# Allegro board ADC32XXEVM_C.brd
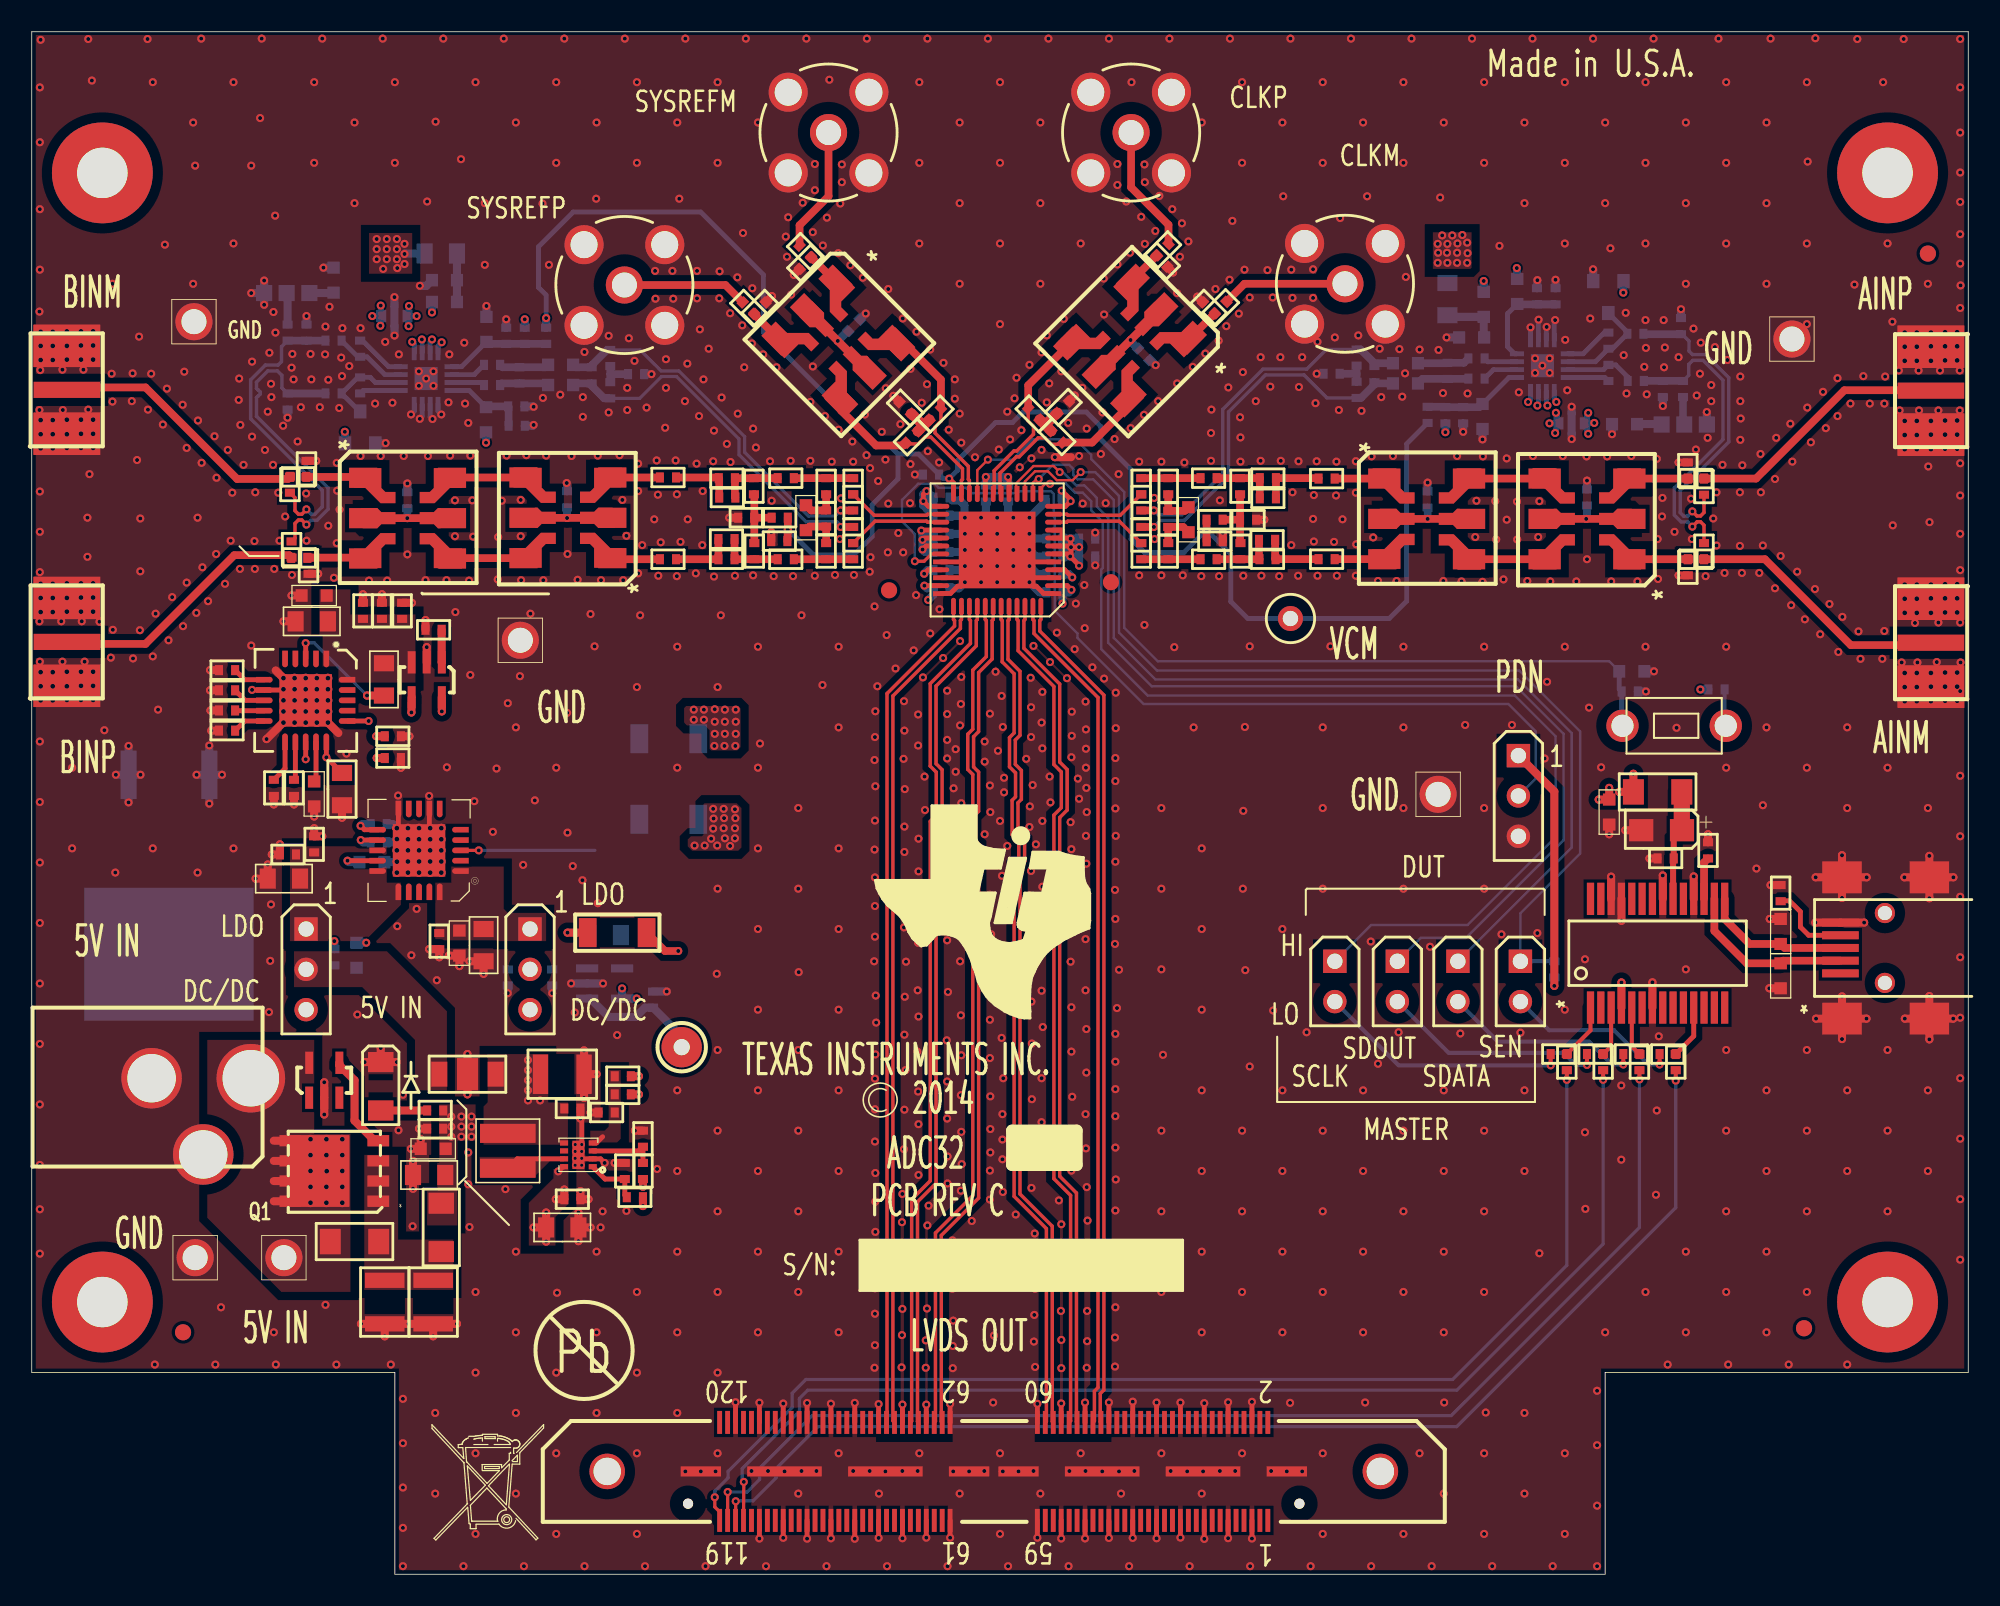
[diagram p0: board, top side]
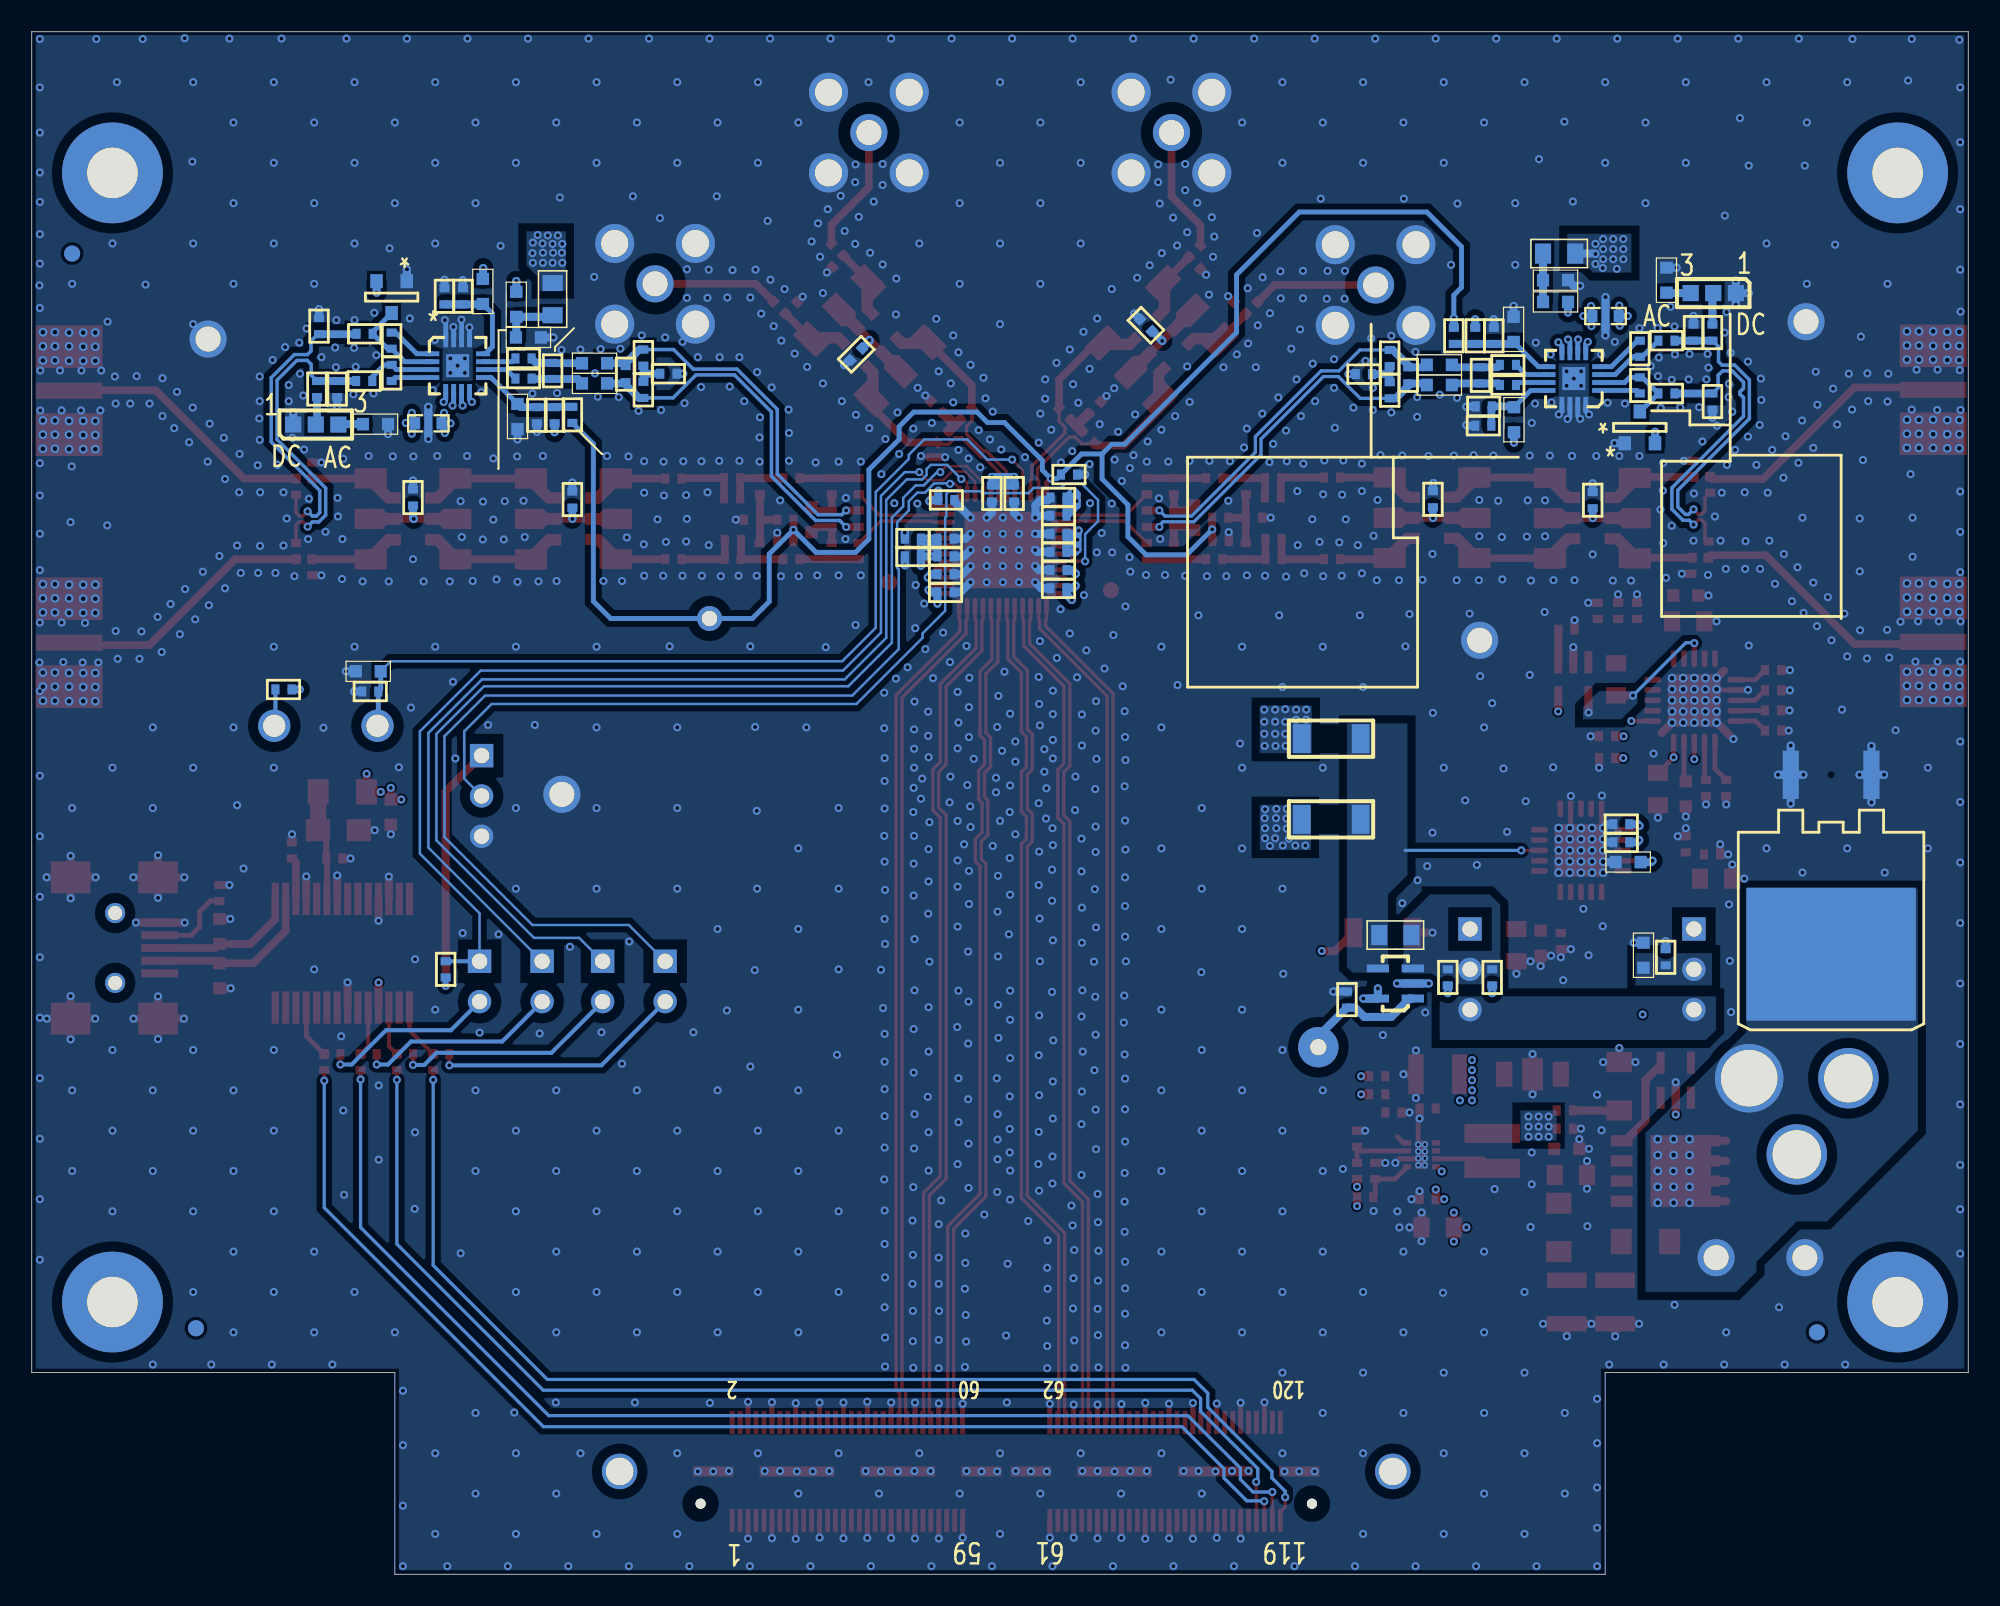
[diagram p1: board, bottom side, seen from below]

Outline 121.92 x 97.16 mm; copper layers: TOP, LYR2_GND, LYR3_PWR, LYR4_PWR, LYR5_GND, BOTTOM. Coordinates in mm from the lower left corner of the outline.
Outline path: 0,97.16 121.92,97.16 121.92,12.7 99.06,12.7 99.06,0 22.86,0 22.86,12.7 0,12.7 0,97.16

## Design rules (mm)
net group AIN: nets AINM AINP
net group BIN: nets BINM BINP
net group CLKIN: nets CLKINM CLKINP
net group DA0: nets DA0M DA0P
net group DA1: nets DA1M DA1P
net group DB0: nets DB0M DB0P
net group DB1: nets DB1M DB1P
net group DCLK: nets DCLKM DCLKP
net group DP1: nets ADCAM ADCAP
net group DP2: nets ADCBM ADCBP
net group DP3: nets AMPAINM AMPAINP
net group DP4: nets AMPBINM AMPBINP
net group DP6: nets A_INM A_INP
net group DP7: nets B_INM B_INP
net group FCLK: nets FCLKM FCLKP
net group SYSREF: nets SYSREFM SYSREFP

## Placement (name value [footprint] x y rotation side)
C1  .1uF  [0402]  81.52 69.01 180 top
C2  11pF  [0402]  71.55 66.47 270 top
C3  .1uF  [0402]  76.58 66.42 180 top
C4  .1uF  [0402]  74.48 65.07 180 top
C5  .1uF  [0402]  97.92 67.82 270 bottom
C6  .1uF  [0402]  87.88 67.69 270 bottom
C7  .1uF  [0402]  81.52 63.94 180 top
C8  .1uF  [0402]  40.06 69.08 0 top
C9  11pF  [0402]  50.01 66.5 270 top
C10  .1uF  [0402]  44.98 66.55 0 top
C11  .1uF  [0402]  47.07 65.07 0 top
C12  .1uF  [0402]  23.64 67.65 270 bottom
C13  .1uF  [0402]  33.7 67.71 270 bottom
C14  .1uF  [0402]  40.06 63.93 0 top
C29  .1uF  [0402]  57.28 64.39 0 bottom
C30  .1uF  [0402]  57.28 65.53 0 bottom
C31  .1uF  [0402]  57.28 66.67 0 bottom
C32  .1uF  [0402]  57.28 67.82 0 bottom
C33  .1uF  [0402]  66.45 65.23 0 bottom
C34  .1uF  [0402]  60.07 68.07 270 bottom
C35  .1uF  [0402]  61.47 68.07 270 bottom
C36  .1uF  [0402]  64.34 67.67 180 bottom
C37  .1uF  [0402]  64.39 65.23 180 bottom
C38  .22uF  [0402]  57.28 63.25 0 bottom
C39  .22uF  [0402]  57.28 62.1 0 bottom
C40  .22uF  [0402]  64.39 61.85 180 bottom
C41  .22uF  [0402]  64.39 62.99 180 bottom
C42  .1uF  [0402]  56.62 69.27 180 bottom
C43  .1uF  [0402]  71.21 83.43 45 top
C44  .1uF  [0402]  74.86 79.79 45 top
C45  .1uF  [0402]  64.94 73.51 45 top
C46  .1uF  [0402]  45.13 79.75 135 top
C47  .1uF  [0402]  48.7 83.32 135 top
C48  .1uF  [0402]  55 73.46 135 top
C49  10nF  [0603]  99.31 48.01 270 top
C50  .1uF  [0402]  102.87 45.09 180 top
C51  4.7uF  [TANT_A]  102.62 46.86 180 top
C52  47pF  [0603]  110.11 40.49 90 top
C53  47pF  [0603]  110.11 37.69 270 top
C54  .1uF  [0402]  105.54 45.59 90 top
C55  47uF  [1210]  22.23 17.14 270 top
C56  22uF  [1210]  25.27 17.14 90 top
C57  10uF  [0805]  25.02 25.15 180 top
C58  1.0uF  [0603]  25.27 26.8 180 top
C59  .1uF  [0402]  25.4 28.07 0 top
C60  .1uF  [0402]  34.04 23.62 180 top
C61  10uF  [0805]  33.4 21.84 0 top
C62  .1uF  [0402]  34.04 29.34 180 top
C63  22uF  [1210]  33.4 31.5 180 top
C64  1.0uF  [0603]  20.45 38.99 90 bottom
C65  .1uF  [0402]  19.05 38.86 270 bottom
C66  0.01uF  [0402]  29.97 37.59 90 bottom
C67  10uF  [0805]  15.88 43.81 180 top
C68  0.01uF  [0402]  16.13 45.34 0 top
C69  .1uF  [0402]  25.65 39.88 270 top
C70  .1uF  [0402]  17.78 45.97 270 top
C71  1.0uF  [0603]  26.92 39.75 270 top
C72  .1uF  [0402]  32.77 37.59 90 bottom
C73  47uF  [0805]  28.45 39.62 270 top
C74  1.0uF  [0603]  21.41 44.86 0 bottom
C160  0.22uF  [C-0603_X2Y]  96.95 72.49 180 bottom
C168  .01uF  [0603]  100.74 56.87 0 bottom
C169  .1uF  [0402]  66.45 64.11 0 bottom
C170  .1uF  [0402]  64.39 64.11 180 bottom
C173  .1uF  [0402]  70.01 76.84 315 bottom
C174  0  [0402]  51.77 78.67 45 bottom
C180  13pF  [0402]  89.13 75.79 270 bottom
C181  56pF  [0402]  84.53 75.59 270 bottom
C187  1.0uF  [0603]  90.65 77.9 180 bottom
C188  .1uF  [0402]  95.94 80.49 270 bottom
C189  10nF  [0603]  28.63 78.41 90 bottom
C190  .1uF  [0402]  22.73 51.41 180 top
C191  0.01uF  [0402]  22.73 52.78 180 top
C192  1.0uF  [0603]  17.78 61.65 180 top
C193  47uF  [0805]  17.63 60.02 180 top
C194  .1uF  [0402]  20.85 60.68 90 top
C195  1.0uF  [0603]  17.78 49.15 270 top
C196  0.01uF  [0402]  22.05 60.68 270 top
C197  10uF  [0805]  19.53 49.45 270 top
C198  .1uF  [0402]  23.32 60.68 270 top
C199  1.0uF  [0603]  25.98 81.51 180 bottom
C200  .1uF  [0402]  30.51 73.56 180 bottom
C205  13pF  [0402]  30.71 75.51 90 bottom
C206  56pF  [0402]  35.26 75.51 90 bottom
C207  1.0uF  [0603]  100.28 72.44 180 bottom
C208  1.0uF  [0603]  19 81.51 90 bottom
C209  10nF  [0603]  91.34 72.92 270 bottom
C210  0.22uF  [C-0603_X2Y]  22.83 79.25 180 bottom
D1  LED GREEN  [LED_1206]  21.97 30.73 90 top
D2  MBRB2515L  [DIODE_MBRB2515L]  8.64 44.7 90 bottom
D3  BAV99  [SOT_23_321]  99.26 80.44 0 bottom
D4  BAV99  [SOT_23_321]  20.68 72.24 180 bottom
F1  FUSE 2.0A 63V FAST  [1206]  20.32 20.95 0 top
FB1  60 OHM @ 100MHz  [1206]  102.36 49.28 180 top
FB2  60 OHM @ 100MHz  [1206]  25.78 21.84 270 top
FB3  27uF  [1206_BEAD_NFM31P]  27.43 31.5 180 top
FB4  1K @ 100MHz  [1806]  40.11 47.55 180 bottom
FB5  1K @ 100MHz  [1806]  40.11 52.63 180 bottom
FB7  1K @ 100MHz  [1806]  36.86 40.41 180 top
FB8  1K @ 100MHz  [0805]  89.13 80.31 90 bottom
FB9  1K @ 100MHz  [0805]  25.76 83.19 180 bottom
J1  SMA_END_RND  [SMA_RECP_250X250]  119.57 74.55 180 top
J2  SMA_END_RND  [SMA_RECP_250X250]  119.57 58.67 180 top
J3  SMA_END_RND  [SMA_RECP_250X250]  2.21 74.6 0 top
J4  SMA_END_RND  [SMA_RECP_250X250]  2.21 58.72 0 top
J9  SMB_THVT_REC  [SMA_THVT_312X312]  69.22 90.8 270 top
J10  SMB_THVT_REC  [SMA_THVT_312X312]  82.68 81.28 270 top
J11  SMB_THVT_REC  [SMA_THVT_312X312]  37.31 81.2 270 top
J12  SMB_THVT_REC  [SMA_THVT_312X312]  50.16 90.8 270 top
J13  QTH-060-01-F-D-A-RT1  [CON_SMVT_120POS_QTH_SAMTEC_RT1]  60.58 6.48 180 top
J14  USB_MINI_AB  [CON_SMRT_USBMNE20_F]  117.32 39.45 180 top
J15  CONN JACK PWR  [CON_RAPC722_JACK_THVT_3]  10.67 31.24 270 top
JP1  Jumper_1x3  [HDR_THVT_1X3_100_M]  93.6 51.56 0 top
JP2  HEADER_1x2_100_430L  [HDR_THVT_1X2_100_M]  82.04 38.61 0 top
JP3  HEADER_1x2_100_430L  [HDR_THVT_1X2_100_M]  89.79 38.61 0 top
JP4  HEADER_1x2_100_430L  [HDR_THVT_1X2_100_M]  93.73 38.61 0 top
JP5  HEADER_1x2_100_430L  [HDR_THVT_1X2_100_M]  85.98 38.61 0 top
JP6  HDR, THVT, 3POS  [HDR_THVT_1X3_100_M]  17.27 40.64 0 top
JP7  HDR, THVT, 3POS  [HDR_THVT_1X3_100_M]  31.37 40.64 0 top
L1  39nH  [0402]  77.83 67.77 0 top
L2  0  [0402]  74.47 66.42 180 top
L3  11pF  [0603]  72.82 66.42 90 top
L4  39nH  [0402]  77.77 65.15 0 top
L5  39nH  [0402]  43.79 67.82 180 top
L6  0  [0402]  47.09 66.55 0 top
L7  11pF  [0603]  48.74 66.55 90 top
L8  39nH  [0402]  43.74 65.2 180 top
L17  1uH  [IND_SM_LQH44P_1515]  29.97 26.67 90 top
L23  150nH  [0603]  86.49 76.28 180 bottom
L24  150nH  [0603]  86.49 75.01 180 bottom
L26  150nH  [0603]  33.3 74.9 0 bottom
L27  150nH  [0603]  33.3 76.17 0 bottom
NOREF  -  []  28.65 5.94 0 top
NOREF#2  -  [unnamed#2]  9.53 15.24 0 top
NOREF#3  -  []  -294.31 -159.02 0 top
NOREF#4  -  [unnamed#2]  111.58 15.49 0 top
NOREF#5  -  []  -294.54 -158.47 0 top
NOREF#6  -  [unnamed#3]  4.45 88.27 0 top
NOREF#7  -  []  99.06 0 90 top
NOREF#8  -  []  99.06 12.7 0 top
NOREF#9  -  [unnamed#3]  116.84 17.14 0 top
NOREF#10  -  []  0 12.7 0 top
NOREF#11  -  []  -276.61 355.97 0 top
NOREF#12  -  []  158.04 -35.71 0 top
NOREF#13  -  []  56.13 -12.98 0 top
NOREF#14  -  []  304.24 154.81 0 top
NOREF#15  -  []  312.88 178.16 0 top
NOREF#16  -  []  49.61 20.27 0 top
NOREF#17  -  [unnamed#3]  4.45 17.14 0 top
NOREF#18  -  [unnamed#2]  119.38 83.19 0 top
NOREF#19  -  []  -177.98 -71.46 0 top
NOREF#20  -  []  113.33 -34.38 0 top
NOREF#21  -  []  4.45 17.14 90 top
NOREF#22  -  []  0 97.16 0 top
NOREF#23  -  []  88.29 -62.33 0 top
NOREF#24  -  [unnamed#2]  53.98 61.98 0 top
NOREF#25  -  [unnamed#3]  116.84 88.27 0 top
NOREF#26  -  []  0 12.7 90 top
NOREF#27  -  []  4.45 88.27 0 top
NOREF#28  -  [unnamed#2]  67.94 62.48 0 top
NOREF#29  -  []  22.86 0 90 top
NOREF#30  -  [unnamed#2]  119.38 83.19 180 bottom
NOREF#31  -  [unnamed#2]  9.53 15.24 180 bottom
NOREF#32  -  [unnamed#2]  111.58 15.49 180 bottom
Q1  CSD18532Q5  [SON_Q5B_8]  19.05 25.4 180 top
R1  49.9  [0402]  77.83 69.04 180 top
R2  0  [0402]  74.09 69.04 180 top
R3  0  [0402]  69.85 68.53 270 top
R4  0  [0402]  104.78 69.01 180 top
R5  24.9  [0402]  76.07 68.53 270 top
R6  49.9  [0402]  71.55 68.53 270 top
R7  0  [0402]  104.27 69.52 90 top
R8  0  [0402]  104.78 63.93 180 top
R9  24.9  [0402]  76.1 64.44 270 top
R10  49.9  [0402]  71.55 64.44 270 top
R11  0  [0402]  104.27 63.42 270 top
R12  49.9  [0402]  77.8 63.94 180 top
R13  0  [0402]  74.09 63.93 180 top
R14  0  [0402]  69.85 64.44 90 top
R15  49.9  [0402]  43.76 69.03 0 top
R16  0  [0402]  47.47 69.04 0 top
R18  0  [0402]  16.84 64.02 0 top
R19  49.9  [0402]  50.01 68.53 270 top
R20  0  [0402]  17.42 63.52 270 top
R21  24.9  [0402]  45.47 68.53 270 top
R22  24.9  [0402]  45.49 64.44 270 top
R23  0  [0402]  16.78 69.12 0 top
R24  49.9  [0402]  50.01 64.44 270 top
R25  0  [0402]  17.3 69.62 90 top
R26  49.9  [0402]  43.74 63.93 0 top
R27  0  [0402]  47.47 63.93 0 top
R57  1K  [0402]  95.86 38.1 90 bottom
R58  10K  [0402]  100.61 55.6 0 bottom
R59  49.9  [0402]  71.14 82.71 315 top
R60  100  [0402]  64.55 71.64 315 top
R61  100  [0402]  63.09 73.09 315 top
R62  0  [0402]  74.1 79.75 135 top
R63  49.9  [0402]  45.84 79.75 45 top
R64  100  [0402]  56.88 73.09 45 top
R65  0  [0402]  48.72 82.58 225 top
R66  100  [0402]  55.43 71.63 45 top
R67  0  [0402]  96.65 32.26 90 top
R68  0  [0402]  101.22 32.26 90 top
R69  0  [0402]  98.93 32.26 90 top
R70  0  [0402]  103.5 32.26 90 top
R71  22  [0402]  100.71 32.77 0 top
R72  22  [0402]  96.14 32.77 0 top
R73  22  [0402]  98.43 32.77 0 top
R74  22  [0402]  103 32.77 0 top
R75  1K  [0402]  25.4 29.21 180 top
R76  0  [0402]  37.97 23.75 180 top
R77  0  [0402]  38.48 25.4 90 top
R78  105K  [0402]  37.21 30.23 180 top
R79  143K  [0402]  37.21 31.37 180 top
R80  0  [0402]  37.34 25.4 90 top
R81  0  [0402]  38.48 27.43 90 top
R82  20K  [0402]  36.2 29.08 180 top
R83  25.5K  [0402]  39.12 36.2 90 bottom
R84  0  [0402]  21.84 46.1 180 bottom
R85  0  [0402]  21.84 47.24 180 bottom
R86  0  [0402]  110.11 42.9 90 top
R87  1K  [0402]  106.07 55.73 0 bottom
R92  205  [0402]  100.97 78.13 180 bottom
R93  205  [0402]  100.99 75.16 180 bottom
R94  499  [0402]  99.26 77.7 270 bottom
R95  499  [0402]  99.26 75.67 90 bottom
R96  59  [0402]  102.69 74.65 270 bottom
R97  49.9  [0402]  103.96 74.65 90 bottom
R98  59  [0402]  103.84 78.61 90 bottom
R101  287  [0402]  83.41 74.6 90 bottom
R104  732  [0402]  32.39 78 270 bottom
R106  2  [0603]  91.41 79.98 90 bottom
R107  20K  [0603]  93.52 80.8 270 bottom
R108  49.9  [0402]  94.77 80.49 270 bottom
R109  44.2  [0402]  90.96 76.58 180 bottom
R110  44.2  [0402]  90.96 75.31 180 bottom
R113  0  [0402]  15.24 49.53 90 top
R114  0  [0402]  16.51 49.53 90 top
R115  25.5K  [0402]  25.3 59.49 180 top
R116  0  [0402]  12.29 53.14 0 top
R117  0  [0402]  12.29 54.41 0 top
R118  0  [0402]  12.29 55.68 0 top
R119  0  [0402]  12.29 56.95 0 top
R120  3.24  [0402]  69.85 67.51 270 top
R121  3.24  [0402]  69.85 65.46 270 top
R122  2  [0603]  25.98 80.14 180 bottom
R123  20K  [0603]  28.6 72.72 90 bottom
R124  49.9  [0402]  30.53 72.34 180 bottom
R125  44.2  [0402]  28.98 74.9 0 bottom
R126  44.2  [0402]  28.98 76.17 0 bottom
R127  205  [0402]  19 74.37 0 bottom
R128  205  [0402]  19 77.7 0 bottom
R129  499  [0402]  20.68 74.88 90 bottom
R130  499  [0402]  20.68 77.19 270 bottom
R131  59  [0402]  17.3 78.21 90 bottom
R132  49.9  [0402]  16.1 78.21 270 bottom
R133  59  [0402]  16.1 73.86 270 bottom
R134  287  [0402]  36.42 76.61 270 bottom
R135  0  [0402]  105.28 68.5 270 top
R136  0  [0402]  105.28 64.44 270 top
R137  0  [0402]  16.26 68.63 270 top
R138  0  [0402]  16.36 64.54 270 top
R139  0  [0402]  51.71 68.53 270 top
R141  3.24  [0402]  51.71 67.51 270 top
R142  0  [0402]  51.71 64.44 90 top
R144  3.24  [0402]  51.71 65.46 270 top
R149  732  [0402]  87.88 73.03 90 bottom
R150  11K  [0402]  89 73 270 bottom
R151  100  [0402]  90.12 73 270 bottom
R152  11K  [0402]  31.04 78 90 bottom
R153  100  [0402]  29.87 78 90 bottom
R154  287  [0402]  36.42 74.57 270 bottom
R155  0  [0402]  38.05 75.59 0 bottom
R156  287  [0402]  83.41 76.63 90 bottom
R157  0  [0402]  81.84 75.62 180 bottom
RS1  0.2  [0805]  36.07 40.26 180 bottom
RS2  0.2  [0805]  22.17 56.36 90 top
SJP1  Jumper_1x3_SMT  [SJP3_JUMPER_0603]  104.04 72.42 180 bottom
SJP2  Jumper_1x3_SMT  [SJP3_JUMPER_0603]  16.05 80.7 0 bottom
SW1  SW PUSHBUTTON  [SW_RESET_PTS635]  103.4 53.44 0 top
T1  ADT1-1WT  [TFMR_6_RF_DUAL_FOOTPRINT]  97.92 66.47 90 top
T2  ADT1-1WT  [TFMR_6_RF_DUAL_FOOTPRINT]  87.82 66.47 270 top
T3  ADT1-1WT  [TFMR_6_RF_DUAL_FOOTPRINT]  23.66 66.52 270 top
T4  ADT1-1WT  [TFMR_6_RF_DUAL_FOOTPRINT]  33.75 66.54 90 top
T9  ADT4-6WT+  [TFMR_6_RF_DUAL_FOOTPRINT]  69.15 77.7 135 top
T10  ADT4-6WT+  [TFMR_6_RF_DUAL_FOOTPRINT]  50.78 77.65 225 top
TP1  TP_THVT_060_RND-RED  [TP_THVT_060_RND]  79.25 60.2 0 top
TP4  Testloop_Red  [TESTPOINT_62DIA]  15.88 19.94 0 top
TP5  Testloop_Black  [TESTPOINT_62DIA]  10.29 19.94 0 top
TP8  RED  [TP_THVT_100_RND]  40.92 33.2 0 top
TP9  Testloop_Black  [TESTPOINT_62DIA]  30.76 58.83 0 top
TP10  Testloop_Black  [TESTPOINT_62DIA]  10.21 78.89 0 top
TP11  Testloop_Black  [TESTPOINT_62DIA]  110.82 77.8 0 top
TP12  Testloop_Black  [TESTPOINT_62DIA]  88.54 49.12 0 top
U1  ADC32XX  [QFN48_RGZ_RTC]  60.78 64.52 180 top
U2  FT245RL  [SSOP_28_413X221_26]  102.36 39.12 90 top
U3  TPS2400  [DBV5]  18.41 31.12 90 top
U4  TPS62080  [SON_DSG_8]  34.42 26.42 180 top
U5  TPS7A4700  [QFN20_RGW_P65PITCH]  24.38 45.59 180 top
U6  INA138  [DBV5]  36.07 37.21 0 bottom
U7  THS4541RGT  [QFN_16_124X124_PWRPAD]  95.11 76.12 180 bottom
U8  TPS7A4700  [QFN20_RGW_P65PITCH]  17.25 55.04 270 top
U9  INA138  [DBV5]  24.87 56.34 270 top
U10  THS4541RGT  [QFN_16_124X124_PWRPAD]  24.83 75.31 0 bottom

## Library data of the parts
C1 C7 C8 C14 = CAP_0402_0.1uF: tolerance: 10%
C2 C9 = CAP0603: tolerance: 1%
C3 C4 C10 C11 = CAP_0402_0.1uF_H: tolerance: 10%
C5 C6 C12 C13 C45 C48 C69 C173 C194 = CAP0603: tolerance: 10%
C29-C37 C42-C44 C46 C47 C169 C170 = CAP0402: tolerance: 10%
C38-C41 = CAP0402: tolerance: +/-10%
C49 C52 C53 = CAP0603
C50 C54 C55 C58 C64 C74 C187 C195 C199 C207 C208 = CAP NP_0: tolerance: 10%
C51 = CAP POL-B_10uF_10V: tolerance: 10%
C56 C63 = CAP_1210_22uF
C57 C67 C71 C192 C197 = CAP NP_1: tolerance: 10%
C59 C60 C62 C65 C66 C68 C70 C72 C188 C190 C191 C196 C198 C200 = CAPACITOR_NP_1: tolerance: 10%
C61 = CAP_1206_2.2uF: tolerance: 10%
C73 C193 = CAP0201: tolerance: 10%
C160 C210 = CAP_X2Y
C168 = CAP NP_0: tolerance: 5%
C174 = CAP0603: tolerance: 5%
C180 C205 = CAP_0402_33pF
C181 C206 = CAP_0402_18pF
C189 C209 = CAP_0603_1000pF
D1 = LED_GREEN_1206
D2 = MBRB2515L_5
D3 D4 = DIODE_BAV99
F1 = FUSE_0
FB1 FB2 FB4 FB5 FB7-FB9 = FERRITE_BEAD
FB3 = BEAD_NFM31P
J1-J4 = SMA-END_PLUG_ROUND
J9-J12 = SMA-THVT_142-0701-201_REC
J13 = CON_SMVT_120POS_QTH_SAMTEC
J14 = USB_MINI_AB_MNE20-5G5P10
J15 = CONN JACK PWR
JP1 SJP1 SJP2 = Jumper_1x3_smt
JP2-JP5 = JUMPER_1x2_100
JP6 JP7 = SMD_JUMPER_1x3
L1 L4 L5 L8 = IND_0402
L2 L6 = IND_0402_H
L3 L7 = IND0603: tolerance: 1%
L17 = IND_POWER_1.5uH
L23 L24 L26 L27 = IND0603
Q1 = CSD18532Q5B
R1 R6 R10 R12 R15 R19 R24 R26 = Res_0402_49.9: tolerance: 1%
R2 R13 R16 R27 R120 R121 R135-R138 R141 R144 = Res_0402_Zero
R3 R14 R139 R142 = Res_0402_4.99
R4 R18 R25 R62 R65 R67-R70 R84-R86 R113 R114 R116-R119 = R: tolerance: 5%
R5 R9 R21 R22 = Res_0402_24.9
R7 R8 R20 R23 R155 R157 = RES0603: tolerance: 5%
R11 = R
R57 R59-R61 R63 R64 R66 R87 R97 R104 R108 R124 R132 R149-R153 = RES0603: tolerance: 1%
R58 = R_4: tolerance: 1%
R71-R74 RS1 RS2 = R: tolerance: 1%
R75-R82 = Res_0402_1k
R83 R115 = R_1: tolerance: 1%
R92-R95 R101 R109 R110 R125-R130 R134 R154 R156 = Res_0402_249
R96 R98 R131 R133 = RES0402
R106 R107 R122 R123 = RES0603
SW1 = SW PUSHBUTTON_1
T1-T4 = TFMR_6_WBC1-1TLB
T9 T10 = XFMR_6_JTX-4-10T
TP1 = TP_THVT_060_RND-RED
TP4 TP5 TP9-TP12 = TESTLOOP_BLACK
TP8 = TESTPOINT_BLUE
U1 = ADC32XX
U2 = FT245RL_0
U3 = TPS2400
U4 = TPS62080_SON8
U5 U8 = TPS7A4700
U6 U9 = INA138
U7 U10 = THS4541RGT

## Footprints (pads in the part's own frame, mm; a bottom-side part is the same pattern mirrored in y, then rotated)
0402
  rect 0.508x0.635 smd: 1(-0.508,0) 2(0.508,0)
0603
  rect 0.762x0.787 smd: 1(-0.787,0) 2(0.787,0)
0805
  rect 1.016x1.27 smd: 1(-1.016,0) 2(1.016,0)
1206
  rect 1.321x1.6 smd: 1(-1.524,0) 2(1.524,0)
1206_BEAD_NFM31P
  rect 1.016x1.575 smd: 1(-1.778,0) 3(1.778,0)
  rect 1.321x2.032 smd: 2(0,0)
1210
  rect 0.965x2.489 smd: 1(-1.372,0) 2(1.372,0)
1806
  rect 1.118x1.829 smd: 1(-1.854,0) 2(1.854,0)
C-0603_X2Y
  rect 0.635x0.762 smd: A(-0.83,0) B(0.83,0)
  rect 0.508x0.254 smd: G1(0,0.635) G2(0,-0.635)
CON_RAPC722_JACK_THVT_3
  round 4.318 hole 3.556: 1(0,3.124)
  round 3.81 hole 3.048: 2(0,-3.124) 3(4.801,0.127)
CON_SMRT_USBMNE20_F
  round 1.27 hole 0.889 unplated: (0.65,2.2) (0.65,-2.2)
  rect 2.311x0.508 smd: 1(3.45,1.6) 2(3.45,0.8) 3(3.45,0) 4(3.45,-0.8) 5(3.45,-1.6)
  rect 2.489x2.007 smd: 6(-2.15,-4.45) 7(3.35,-4.45) 8(3.35,4.45) 9(-2.15,4.45)
CON_SMVT_120POS_QTH_SAMTEC_RT1
  round 2.235 hole 1.727: (-24.329,0) (24.35,0)
  round 0.635 hole 1.016 unplated: (-19.233,2.032) (19.258,2.032)
  rect 0.305x1.448 smd: 1(-17.244,3.086) 2(-17.244,-3.086) 3(-16.744,3.086) 4(-16.744,-3.086) 5(-16.243,3.086) 6(-16.243,-3.086) 7(-15.743,3.086) 8(-15.743,-3.086) 9(-15.243,3.086) 10(-15.243,-3.086) 11(-14.742,3.086) 12(-14.742,-3.086) 13(-14.242,3.086) 14(-14.242,-3.086) 15(-13.741,3.086) 16(-13.741,-3.086) 17(-13.241,3.086) 18(-13.241,-3.086) 19(-12.741,3.086) 20(-12.741,-3.086) 21(-12.24,3.086) 22(-12.24,-3.086) 23(-11.74,3.086) 24(-11.74,-3.086) 25(-11.239,3.086) 26(-11.239,-3.086) 27(-10.739,3.086) 28(-10.739,-3.086) 29(-10.239,3.086) 30(-10.239,-3.086) 31(-9.738,3.086) 32(-9.738,-3.086) 33(-9.238,3.086) 34(-9.238,-3.086) 35(-8.738,3.086) 36(-8.738,-3.086) 37(-8.237,3.086) 38(-8.237,-3.086) 39(-7.737,3.086) 40(-7.737,-3.086) 41(-7.236,3.086) 42(-7.236,-3.086) 43(-6.736,3.086) 44(-6.736,-3.086) 45(-6.236,3.086) 46(-6.236,-3.086) 47(-5.735,3.086) 48(-5.735,-3.086) 49(-5.235,3.086) 50(-5.235,-3.086) 51(-4.735,3.086) 52(-4.735,-3.086) 53(-4.234,3.086) 54(-4.234,-3.086) 55(-3.734,3.086) 56(-3.734,-3.086) 57(-3.233,3.086) 58(-3.233,-3.086) 59(-2.733,3.086) 60(-2.733,-3.086) 61(2.758,3.086) 62(2.758,-3.086) 63(3.259,3.086) 64(3.259,-3.086) 65(3.759,3.086) 66(3.759,-3.086) 67(4.26,3.086) 68(4.26,-3.086) 69(4.76,3.086) 70(4.76,-3.086) 71(5.26,3.086) 72(5.26,-3.086) 73(5.761,3.086) 74(5.761,-3.086) 75(6.261,3.086) 76(6.261,-3.086) 77(6.761,3.086) 78(6.761,-3.086) 79(7.262,3.086) 80(7.262,-3.086) 81(7.762,3.086) 82(7.762,-3.086) 83(8.263,3.086) 84(8.263,-3.086) 85(8.763,3.086) 86(8.763,-3.086) 87(9.263,3.086) 88(9.263,-3.086) 89(9.764,3.086) 90(9.764,-3.086) 91(10.264,3.086) 92(10.264,-3.086) 93(10.765,3.086) 94(10.765,-3.086) 95(11.265,3.086) 96(11.265,-3.086) 97(11.765,3.086) 98(11.765,-3.086) 99(12.266,3.086) 100(12.266,-3.086) 101(12.766,3.086) 102(12.766,-3.086) 103(13.266,3.086) 104(13.266,-3.086) 105(13.767,3.086) 106(13.767,-3.086) 107(14.267,3.086) 108(14.267,-3.086) 109(14.768,3.086) 110(14.768,-3.086) 111(15.268,3.086) 112(15.268,-3.086) 113(15.768,3.086) 114(15.768,-3.086) 115(16.269,3.086) 116(16.269,-3.086) 117(16.769,3.086) 118(16.769,-3.086) 119(17.269,3.086) 120(17.269,-3.086)
  rect 2.54x0.635 smd: 121(-18.438,0) 124(-1.547,0) 125(1.565,0) 128(18.456,0)
  rect 4.699x0.635 smd: 122(-13.167,0) 123(-6.817,0) 126(6.835,0) 127(13.185,0)
DBV5
  rect 1.4x0.5 smd: 1(-1.1,0.95) 2(-1.1,0) 3(-1.1,-0.95) 4(1.1,-0.95) 5(1.1,0.95)
DIODE_MBRB2515L
  rect 3.048x1.016 smd: 1(5.652,-2.54) 3(5.652,2.54)
  round 0.013 smd: 2(5.652,0)
  rect 8.382x10.668 smd: 4(-5.652,0)
HDR_THVT_1X2_100_M
  rect 1.473x1.473 hole 0.965: 1(0,0)
  round 1.473 hole 0.965: 2(0,-2.54)
HDR_THVT_1X3_100_M
  rect 1.473x1.473 hole 0.965: 1(0,0)
  round 1.473 hole 0.965: 2(0,-2.54) 3(0,-5.08)
IND_SM_LQH44P_1515
  rect 1.2x3.5 smd: 1(-1.1,0) 2(1.1,0)
LED_1206
  rect 1.27x1.6 smd: 1(-1.524,0) 2(1.524,0)
QFN20_RGW_P65PITCH
  custom 0.09x0.09 smd: 1(-2.607,1.3) 2(-2.607,0.65) 3(-2.607,0) 4(-2.607,-0.65) 5(-2.607,-1.3) 6(-1.3,-2.607) 7(-0.65,-2.607) 8(0,-2.607) 9(0.65,-2.607) 10(1.3,-2.607) 11(2.607,-1.3) 12(2.607,-0.65) 13(2.607,0) 14(2.607,0.65) 15(2.607,1.3) 16(1.3,2.607) 17(0.65,2.607) 18(0,2.607) 19(-0.65,2.607) 20(-1.3,2.607)
  rect 3.302x3.302 smd: 21(0,0)
QFN48_RGZ_RTC
  custom 0.076x0.076 smd: 1(-3.525,2.75) 2(-3.525,2.25) 3(-3.525,1.75) 4(-3.525,1.25) 5(-3.525,0.75) 6(-3.525,0.25) 7(-3.525,-0.25) 8(-3.525,-0.75) 9(-3.525,-1.25) 10(-3.525,-1.75) 11(-3.525,-2.25) 12(-3.525,-2.75) 13(-2.75,-3.525) 14(-2.25,-3.525) 15(-1.75,-3.525) 16(-1.25,-3.525) 17(-0.75,-3.525) 18(-0.25,-3.525) 19(0.25,-3.525) 20(0.75,-3.525) 21(1.25,-3.525) 22(1.75,-3.525) 23(2.25,-3.525) 24(2.75,-3.525) 25(3.525,-2.75) 26(3.525,-2.25) 27(3.525,-1.75) 28(3.525,-1.25) 29(3.525,-0.75) 30(3.525,-0.25) 31(3.525,0.25) 32(3.525,0.75) 33(3.525,1.25) 34(3.525,1.75) 35(3.525,2.25) 36(3.525,2.75) 37(2.75,3.525) 38(2.25,3.525) 39(1.75,3.525) 40(1.25,3.525) 41(0.75,3.525) 42(0.25,3.525) 43(-0.25,3.525) 44(-0.75,3.525) 45(-1.25,3.525) 46(-1.75,3.525) 47(-2.25,3.525) 48(-2.75,3.525)
  rect 4.826x4.826 smd: 49(0,0)
QFN_16_124X124_PWRPAD
  rect 0.889x0.305 smd: 1(-1.6,0.749) 2(-1.6,0.249) 3(-1.6,-0.249) 4(-1.6,-0.749) 9(1.6,-0.749) 10(1.6,-0.249) 11(1.6,0.249) 12(1.6,0.749)
  rect 0.305x0.889 smd: 5(-0.749,-1.6) 6(-0.249,-1.6) 7(0.249,-1.6) 8(0.749,-1.6) 13(0.749,1.6) 14(0.249,1.6) 15(-0.249,1.6) 16(-0.749,1.6)
  rect 1.45x1.45 smd: 17(0,0)
SJP3_JUMPER_0603
  rect 1.016x1.016 smd: 1(-1.422,0) 2(0,0) 3(1.422,0)
SMA_RECP_250X250
  rect 4.191x1.016 smd: 1(0,0)
  rect 4.191x2.667 smd: 2(0,2.769) 3(0,-2.769) 4(0,2.769) 5(0,-2.769)
SMA_THVT_312X312
  round 2.337 hole 1.575: 1(0,0)
  round 2.464 hole 1.702: 2(-2.54,2.54) 3(2.54,2.54) 4(2.54,-2.54) 5(-2.54,-2.54)
SON_DSG_8
  rect 0.508x0.33 smd: 1(-0.903,0.75) 2(-0.903,0.25) 3(-0.903,-0.25) 4(-0.903,-0.75) 5(0.903,-0.75) 6(0.903,-0.25) 7(0.903,0.25) 8(0.903,0.75)
  rect 0.762x1.778 smd: 9(0,0)
SON_Q5B_8
  rect 1.372x0.711 smd: 1(-2.767,1.905) 2(-2.767,0.635) 3(-2.767,-0.635) 4(-2.767,-1.905) 5(2.767,-1.905) 6(2.767,-0.635) 7(2.767,0.635) 8(2.767,1.905)
SOT_23_321
  rect 0.787x0.889 smd: 1(-0.953,-1.003) 2(0.953,-1.003) 3(0,1.003)
SSOP_28_413X221_26
  rect 2.032x0.457 smd: 1(-3.425,4.225) 2(-3.425,3.575) 3(-3.425,2.925) 4(-3.425,2.275) 5(-3.425,1.625) 6(-3.425,0.975) 7(-3.425,0.325) 8(-3.425,-0.325) 9(-3.425,-0.975) 10(-3.425,-1.625) 11(-3.425,-2.275) 12(-3.425,-2.925) 13(-3.425,-3.575) 14(-3.425,-4.225) 15(3.425,-4.225) 16(3.425,-3.575) 17(3.425,-2.925) 18(3.425,-2.275) 19(3.425,-1.625) 20(3.425,-0.975) 21(3.425,-0.325) 22(3.425,0.325) 23(3.425,0.975) 24(3.425,1.625) 25(3.425,2.275) 26(3.425,2.925) 27(3.425,3.575) 28(3.425,4.225)
SW_RESET_PTS635
  round 2.032 hole 1.397: 1(-3.251,0) 2(3.251,0)
TANT_A
  rect 1.524x1.397 smd: 1(-1.283,0) 2(1.283,0)
TESTPOINT_62DIA
  round 2.337 hole 1.575: 1(0,0)
TFMR_6_RF_DUAL_FOOTPRINT
  rect 1.27x1.778 smd: 1(-2.54,-2.794) 2(0,-2.794) 3(2.54,-2.794) 4(2.54,2.794) 5(0,2.794) 6(-2.54,2.794)
TP_THVT_060_RND
  round 1.575 hole 0.965: 1(0,0)
TP_THVT_100_RND
  round 2.54 hole 1.016: 1(0,0)
unnamed#2
  round 1.016 smd: 1(0,0)
unnamed#3
  round 6.35 hole 3.175: (0,0)

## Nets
1.8V: JP6.3(PIN3) JP7.3(PIN3)
2.8V_IN: C67.1 C68.2 C70.2 JP6.1(PIN1) U5.13(EN) U5.15(IN2) U5.16(IN1)
5.0V_IN: D2.4 F1.1 J15.1 Q1.5(D5) Q1.6(D6) Q1.7(D7) Q1.8(D8) TP4.1(TP) U3.5(VIN)
5VIN: C49.1 C57.1 C58.1 C59.2 C60.2 C61.1 C190.2 C191.2 C197.1 FB1.2 FB2.1 R75.1 R76.1 R77.1 U4.8(VIN) U6.5(V+) U8.13(EN) U8.15(IN2) U8.16(IN1) U9.5(V+)
+VCC: FB8.2 FB9.2 RS2.1 U8.3(SENSE) U9.4(VIN-)
AVDD1.8V: C29.1 C30.1 C31.1 C32.1 C33.1 C34.1 C35.1 C36.1 C37.1 C169.1 C170.1 FB5.1 U1.6(AVDD#6) U1.7(AVDD#7) U1.8(AVDD#8) U1.9(AVDD#9) U1.12(AVDD#12) U1.17(AVDD#17) U1.20(AVDD#20) U1.25(AVDD#25) U1.28(AVDD#28) U1.29(AVDD#29) U1.30(AVDD#30)
DVDD1.8V: C38.1 C39.1 C40.1 C41.1 FB4.1 JP1.1(PIN1) R57.1 R87.1 U1.2(DVDD#2) U1.4(DVDD#4) U1.33(DVDD#33) U1.35(DVDD#35)
GND: C3.1 C4.1 C5.1 C6.1 C10.1 C11.1 C12.1 C13.1 C29.2 C30.2 C31.2 C32.2 C33.2 C34.2 C35.2 C36.2 C37.2 C38.2 C39.2 C40.2 C41.2 C42.2 C45.2 C48.2 C49.2 C50.2 C51.2 C52.2 C53.2 C54.2 C55.2 C56.1 C57.2 C58.2 C59.1 C60.1 C61.2 C62.1 C63.1 C64.2 C65.1 C66.1 C67.2 C68.1 C69.2 C70.1 C71.2 C72.1 C73.2 C74.2 C160.G1 C160.G2 C168.2 C169.2 C170.2 C173.2 C174.2 C187.2 C188.1 C189.2 C190.1 C191.1 C192.2 C193.2 C194.2 C195.2 C196.1 C197.2 C198.1 C199.2 C200.1 C207.2 C208.2 C209.2 C210.G1 C210.G2 D1.2(CATHODE) D2.1 D2.3 D3.1 D4.1 FB3.2 J1.2(SHIELD2) J1.3(SHIELD3) J1.4(SHIELD4) J1.5(SHIELD1) J2.2(SHIELD2) J2.3(SHIELD3) J2.4(SHIELD4) J2.5(SHIELD1) J3.2(SHIELD2) J3.3(SHIELD3) J3.4(SHIELD4) J3.5(SHIELD1) J4.2(SHIELD2) J4.3(SHIELD3) J4.4(SHIELD4) J4.5(SHIELD1) J9.2(GND#2) J9.3(GND#3) J9.4(GND#4) J9.5(GND#5) J10.2(GND#2) J10.3(GND#3) J10.4(GND#4) J10.5(GND#5) J11.2(GND#2) J11.3(GND#3) J11.4(GND#4) J11.5(GND#5) J12.2(GND#2) J12.3(GND#3) J12.4(GND#4) J12.5(GND#5) J13.5 J13.6 J13.11 J13.12 J13.17 J13.18 J13.23 J13.24 J13.29 J13.30 J13.35 J13.36 J13.41 J13.42 J13.47 J13.48 J13.53 J13.54 J13.59 J13.60 J13.61 J13.62 J13.67 J13.68 J13.73 J13.74 J13.79 J13.80 J13.85 J13.86 J13.91 J13.92 J13.97 J13.98 J13.103 J13.104 J13.109 J13.110 J13.116 J13.121(GND#121) J13.122(GND#122) J13.123(GND#123) J13.124(GND#124) J13.125(GND#125) J13.126(GND#126) J13.127(GND#127) J13.128(GND#128) J14.5(GND) J14.6(GND1) J14.7(GND2) J14.8(GND3) J14.9(GND4) J15.2 J15.3 JP1.3(PIN3) R7.2 R11.2 R20.2 R25.2 R58.2 R59.2 R62.2 R63.2 R65.2 R80.2 R81.2 R82.2 R83.2 R84.1 R85.1 R86.2 R96.2 R98.2 R108.1 R113.1 R114.1 R115.2 R116.1 R117.1 R118.1 R119.1 R124.1 R131.2 R133.2 R151.2 R153.2 R155.2 R157.2 SJP1.1(PIN1) SJP2.1(PIN1) TP5.1(TP) TP9.1(TP) TP10.1(TP) TP11.1(TP) TP12.1(TP) U1.1(GND#1) U1.3(GND#3) U1.5(GND#5) U1.32(GND#32) U1.34(GND#34) U1.36(GND#36) U1.49(THERMPAD) U2.7(GND#7) U2.18(GND#18) U2.21(GND#21) U2.25(AGND) U2.26(TEST) U3.2(GND) U4.2(GND) U4.9(THERMPAD) U5.7(GND) U5.10(0P4V) U5.21(PWRPAD) U6.2(GND) U7.13(VS1-) U7.14(VS2-) U7.15(VS3-) U7.16(VS4-) U7.17(PWRPAD) U8.7(GND) U8.21(PWRPAD) U9.2(GND) U10.13(VS1-) U10.14(VS2-) U10.15(VS3-) U10.16(VS4-) U10.17(PWRPAD)
A_INM: J2.1(CENTER) R8.1 R136.2
A_INP: J1.1(CENTER) R4.1 R135.1
ADCAM: C181.2 L24.2 R101.1 R121.1
ADCAP: C181.1 L23.2 R120.2 R156.2
ADCBM: C206.1 L26.2 R144.1 R154.2
ADCBP: C206.2 L27.2 R134.1 R141.2
AINM: R14.2 R121.2 U1.10(INP_A)
AINP: R3.2 R120.1 U1.11(INM_A)
AMPAINM: R93.1 R96.1 R97.2 R136.1
AMPAINP: R92.1 R98.1 R135.2
AMPBINM: R127.1 R133.1 R138.1
AMPBINP: R128.1 R131.1 R132.2 R137.2
B_INM: J3.1(CENTER) R23.1 R137.1
B_INP: J4.1(CENTER) R18.1 R138.2
BINM: R142.2 R144.2 U1.27(INP_B)
BINP: R139.2 R141.1 U1.26(INM_B)
CLKINM: R61.1 T9.4(SECONDARY) U1.19(CLKM)
CLKINP: R60.2 T9.6(SECONDARY_DOT) U1.18(CLKP)
CLOCK_INM: C44.2 J10.1(CENTER)
CLOCK_INP: C43.2 J9.1(CENTER)
DA0M: J13.44 U1.48(DA0M)
DA0P: J13.46 U1.47(DA0P)
DA1M: J13.50 U1.46(DA1M)
DA1P: J13.52 U1.45(DA1P)
DB0M: J13.70 U1.40(DB0M)
DB0P: J13.72 U1.39(DB0P)
DB1M: J13.76 U1.38(DB1M)
DB1P: J13.78 U1.37(DB1P)
DCLKM: J13.56 U1.44(DCLKM)
DCLKP: J13.58 U1.43(DCLKP)
FCLKM: J13.64 U1.42(FCLKM)
FCLKP: J13.66 U1.41(FCLKP)
FPGA_CSEL: J13.115 R70.1
FPGA_SCLK: J13.119 R67.1
FPGA_SDI: J13.117 R68.1
FPGA_SDO: J13.113 R69.1
FTDI_VCCIO1.8V: FB7.1 U2.4(VCCIO)
PDA: C188.2 R107.2 R108.2 U7.12(PD)
PDB: C200.2 R123.2 R124.2 U10.12(PD)
PDN: JP1.2(PIN2) U1.31(PDN)
RESET: C168.1 R58.1 SW1.1 U1.21(RESET)
SCLK: JP2.2 R72.1
SDATA: JP3.2 R71.1
SDOUT: JP5.2 R73.1
SEN: JP4.2 R74.1
SYSREF_INM: C47.2 J12.1(CENTER)
SYSREF_INP: C46.2 J11.1(CENTER)
SYSREFM: R66.1 T10.4(SECONDARY) U1.23(SYSREFM)
SYSREFP: R64.2 T10.6(SECONDARY_DOT) U1.22(SYSREFP)
U5_SENSE: FB4.2 FB5.2 RS1.1 U5.3(SENSE) U6.4(VIN-)
VAMPA: C160.A C160.B D3.2 R106.2 R107.1 R150.2 U7.5(VS1+) U7.6(VS2+) U7.7(VS3+) U7.8(VS4+)
VAMPB: C210.A C210.B D4.2 R122.2 R123.1 R152.2 U10.5(VS1+) U10.6(VS2+) U10.7(VS3+) U10.8(VS4+)
VCM: C4.2 C11.2 C42.1 L2.2 L6.2 R104.1 R149.1 TP1.1(TP) U1.24(VCM)
VCM_AMPA: C209.1 R149.2 R150.1 R151.1 U7.9(VOCM)
VCM_AMPB: C189.1 R104.2 R152.1 R153.1 U10.9(VOCM)
N16255310: C5.2 T1.2(SECONDARY_CT) T1.5(NC)
N16255380: T1.6(PRIMARY_DOT) T2.4(PRIMARY)
N16255412: T1.4(PRIMARY) T2.6(PRIMARY_DOT)
N16255546: C6.2 T2.2(SECONDARY_CT) T2.5(NC)
N16275326: C12.2 T3.2(SECONDARY_CT) T3.5(NC)
N16275406: C14.1 T4.1(SECONDARY_DOT)
N16275410: T3.4(PRIMARY) T4.6(PRIMARY_DOT)
N16275430: T3.6(PRIMARY_DOT) T4.4(PRIMARY)
N16275564: C13.2 T4.2(SECONDARY_CT) T4.5(NC)
N17995731: C7.1 T2.3(SECONDARY)
N18036747: R4.2 R7.1 T1.3(SECONDARY)
N18037025: R8.2 R11.1 T1.1(SECONDARY_DOT)
N18037341: R18.2 R20.1 T3.3(SECONDARY)
N18145356: C44.1 R62.1 T9.1(PRIMARY)
N18145361: C43.1 R59.1 T9.3(PRIMARY_DOT)
N18152532: C1.1 T2.1(SECONDARY_DOT)
N18152657: C8.1 T4.3(SECONDARY)
N18154317: JP2.1 U1.13(SCLK)
N18154319: JP5.1 U1.16(SDOUT)
N18154320: JP4.1 R57.2 U1.15(SEN)
N18154541: JP3.1 U1.14(SDATA)
N18158256: C50.1 C51.1 FB1.1 U2.20(VCC)
N18158298: R69.2 R73.2 U2.3(D2)
N18158304: R67.2 R72.2 U2.1(D0)
N18158332: C53.1 J14.2(D-) U2.16(USBDM)
N18158362: C54.1 U2.17(3V3OUT)
N18158372: C52.1 J14.3(D+) U2.15(USBDP)
N18158488: R68.2 R71.2 U2.5(D1)
N18172592: R23.2 R25.1 T3.1(SECONDARY_DOT)
N18176897: C3.2 L2.1 R5.2 R9.1
N18176915: C2.1 L3.2 R6.2
N18176926: C2.2 L3.1 R10.1
N18176961: R2.2 R3.1 R6.1
N18176965: R10.2 R13.2 R14.1
N18176992: L1.1 R1.2 R2.1 R5.1
N18176994: L4.1 R9.2 R12.2 R13.1
N18177028: C1.2 L1.2 R1.1
N18177046: C7.2 L4.2 R12.1
N18177748: C10.2 L6.1 R21.2 R22.1
N18177758: C9.1 L7.2 R19.2
N18177777: C9.2 L7.1 R24.1
N18177812: R16.2 R19.1 R139.1
N18177816: R24.2 R27.2 R142.1
N18177835: L5.1 R15.2 R16.1 R21.1
N18177837: L8.1 R22.2 R26.2 R27.1
N18177879: C8.2 L5.2 R15.1
N18177897: C14.2 L8.2 R26.1
N18182829: C47.1 R65.1 T10.1(PRIMARY)
N18182834: C46.1 R63.1 T10.3(PRIMARY_DOT)
N18184820: R76.2 R80.1 U4.1(EN)
N18184826: R77.2 R81.1 U4.3(MODE)
N18184858: L17.1 U4.7(SW)
N18184878: C62.2 C63.2 FB3.1 L17.2 R78.1 R79.1 U4.5(VOS)
N18184911: R78.2 R79.2 R82.1 U4.4(FB)
N18184929: C66.2 C72.2 FB7.2 JP7.2(PIN2) RS1.2 U6.3(VIN+)
N18184992: C55.1 C56.2 F1.2 FB2.2 Q1.1(S1) Q1.2(S2) Q1.3(S3)
N18185086: C69.1 C71.1 C73.1 JP7.1(PIN1) U5.1(OUT1) U5.20(OUT2)
N18185106: C74.1 U5.14(NR)
N18185155: R84.2 U5.12(0P1V)
N18185175: R85.2 U5.11(0P2V)
N18185335: C64.1 C65.2 FB3.3 JP6.2(PIN2)
N18185416: R83.1 TP8.1(TP) U6.1(OUT)
N18185709: Q1.4(G) U3.4(GATE)
N18185817: D1.1(ANODE) R75.2
N18186843: R70.2 R74.2 U2.11(D3)
N18187243: J14.4(ID) R86.1
N18187932: R87.2 SW1.2
N18195117: C45.1 R60.1 R61.2
N18195272: C173.1 T9.2(PRIMARY_CT) T9.5(SECONDARY_CT)
N18195497: C48.1 R64.1 R66.2
N18195560: C174.1 T10.2(PRIMARY_CT) T10.5(SECONDARY_CT)
N18236051: C180.1 L23.1 R109.2
N18236057: C180.2 L24.1 R110.2
N18238916: C187.1 FB8.1 R106.1
N18248026: R110.1 U7.10(VOUT+)
N18248246: R109.1 U7.11(VOUT-)
N18248498: R93.2 R95.2 U7.3(VIN-)
N18248506: R95.1 U7.4(FB+)
N18248596: D3.3 R92.2 R94.2 U7.2(VIN+)
N18248639: R94.1 U7.1(FB-)
N18254985: C192.1 C193.1 C194.1 C196.2 C198.2 RS2.2 U8.1(OUT1) U8.20(OUT2) U9.3(VIN+)
N18255095: C195.1 U8.14(NR)
N18255144: R114.2 U8.12(0P1V)
N18255168: R113.2 U8.11(0P2V)
N18255172: R116.2 U8.10(0P4V)
N18255251: R115.1 U9.1(OUT)
N18258500: R117.2 U8.9(0P8V)
N18258503: R118.2 U8.8(1P6V)
N18258506: R119.2 U8.6(3P2V)
N18271567: C199.1 FB9.1 R122.1
N18273924: C205.1 L26.1 R125.2
N18273934: C205.2 L27.1 R126.2
N18274097: R126.1 U10.10(VOUT+)
N18274103: R125.1 U10.11(VOUT-)
N18274115: R128.2 R130.2 U10.3(VIN-)
N18274119: R130.1 U10.4(FB+)
N18274129: D4.3 R127.2 R129.2 U10.2(VIN+)
N18274135: R129.1 U10.1(FB-)
N18283030: C207.1 SJP1.3(PIN3)
N18283930: R97.1 SJP1.2(PIN2)
N18284096: C208.1 SJP2.3(PIN3)
N18284104: R132.1 SJP2.2(PIN2)
N18358536: R134.2 R154.1 R155.1
N18359182: R101.2 R156.1 R157.1

Pads without a net: D2 2; J13 1 2 3 4 7 8 9 10 13 14 15 16 19 20 21 22 25 26 27 28 31 32 33 34 37 38 39 40 43 45 49 51 55 57 63 65 69 71 75 77 81 82 83 84 87 88 89 90 93 94 95 96 99 100 101 102 105 106 107 108 111 112 114 118 120; J14 1; NOREF#2 1; NOREF#4 1; NOREF#18 1; NOREF#24 1; NOREF#28 1; NOREF#30 1; NOREF#31 1; NOREF#32 1; U2 2 6 8 9 10 12 13 14 19 22 23 24 27 28; U3 1 3; U4 6; U5 2 4 5 6 8 9 17 18 19; U8 2 4 5 17 18 19

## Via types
v1: diameter 0.508, hole 0.254, TOP to BOTTOM, 1764 vias
v2: diameter 0.559, hole 0.305, TOP to BOTTOM, 185 vias
v3: diameter 0.406, hole 0.203, TOP to BOTTOM, 8 vias

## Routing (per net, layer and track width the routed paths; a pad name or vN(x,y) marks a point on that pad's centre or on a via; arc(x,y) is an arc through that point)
5.0V_IN: length 28.8
  TOP w0.254: v2(17.55,26.4) v2(17.55,27.4) ; v2(17.55,26.4) v2(17.55,25.4) ; v2(17.55,26.4) v2(18.55,26.4) ; v2(17.55,27.4) 17.45,27.3 Q1.5 ; v2(17.55,27.4) v2(18.55,27.4) ; v2(18.57,25.39) 18.57,26.38 v2(18.55,26.4) ; v2(18.57,25.39) 18.58,25.4 v2(19.55,25.4) ; v2(18.57,25.39) 17.56,25.39 v2(17.55,25.4) ; v2(18.57,25.39) 18.55,25.37 v2(18.55,24.4) ; v2(19.55,24.4) v2(18.55,24.4) ; v2(19.55,24.4) v2(19.55,25.4) ; v2(19.55,24.4) v2(19.55,23.4) v2(18.55,23.4) ; v2(18.55,24.4) v2(17.55,24.4) ; v2(18.55,24.4) v2(18.55,23.4) ; v2(17.55,25.4) v2(17.55,24.4) ; v2(18.55,26.4) v2(19.55,26.4) ; v2(18.55,26.4) v2(18.55,27.4) ; v2(18.55,27.4) v2(19.55,27.4) v2(19.55,26.4) ; v2(19.55,26.4) v2(19.55,25.4) ; Q1.8 17.45,23.49 v2(17.55,23.4) ; v2(18.55,23.4) v2(17.55,23.4) ; v2(17.55,23.4) v2(17.55,24.4)
  TOP w0.508: Q1.5 15.24,27.3 ; Q1.7 15.24,24.77 ; Q1.6 15.24,26.04 ; Q1.8 15.24,23.49
5VIN: length 17
  TOP w0.305: v1(33.15,25.37) 33.44,25.67 U4.8 ; U8.15 v1(18.55,51.46) C197.1 ; U8.13 v1(17.25,51.33) ; U8.16 v1(21.21,53.74)
  TOP w0.508: C61.1 v1(32.39,20.95) ; C61.1 v1(31.6,21.84) ; C61.1 v1(32.39,22.78) ; v1(32.99,23.62) C60.2 v1(33.53,24.23) ; v1(99.31,49.53) C49.1 v1(98.65,48.79) ; C190.2 v1(21.72,51.41) ; C191.2 v1(21.69,52.78) ; v1(99.95,49.28) FB1.2 v1(100.84,50.42) ; R76.1 v1(38.48,23.19) ; R77.1 v1(38.48,24.41) ; U9.5 v1(25.82,54.35)
  BOTTOM w0.508: v1(38.09,36.26) U6.5 v1(37.17,36.9)
  vias: v1(26.42,28.83) v1(26.42,28.19) v1(26.42,27.56) v1(27.05,28.83) v1(27.05,28.19) v1(27.05,27.56) v1(27.69,28.83) v1(27.69,28.19) v1(27.69,27.56)
+VCC: length 9.6
  TOP w0.305: U8.3 v1(17.25,58.65)
  TOP w0.508: RS2.1 v1(21.11,55.35) ; U9.4 v1(23.9,54.28)
  BOTTOM w0.203: v1(17.25,58.65) 17.27,58.67 17.78,58.67 v1(21.11,55.35)
  BOTTOM w0.508: v1(23.47,83.16) 23.5,83.19 FB9.2
  vias: v1(21.72,84.1) v1(21.72,83.46) v1(21.72,82.83) v1(22.12,82.22) v1(22.35,84.1) v1(22.35,83.46) v1(22.35,82.83) v1(22.99,84.1) v1(22.99,83.46) v1(22.99,82.83) v1(23.01,82.27) v1(23.47,83.79) v1(23.47,82.52) v1(88.52,83.79) v1(88.54,83.24) v1(88.52,82.6) v1(88.8,84.33) v1(89.13,83.79) v1(89.1,83.24) v1(89.13,82.6) v1(89.43,84.33) v1(89.76,83.82) v1(89.74,83.24) v1(89.74,82.6) v1(90.07,84.35) v1(90.37,83.87) v1(90.37,82.6) v1(90.4,83.21)
AVDD1.8V: length 38.1
  TOP w0.305: U1.9 64.87,65.77 64.87,65.27 ; U1.28 56.04,65.77 v1(56.01,65.74) ; U1.8 64.87,65.27 ; 64.87,65.27 65.37,65.27 v1(65.41,65.23) 65.41,64.77 ; U1.20 60.03,69.07 v1(60.07,69.11) ; v1(61.47,69.11) 61.53,69.05 U1.17 ; U1.7 65.41,64.77 ; 65.41,64.77 65.41,64.72 v1(65.43,64.69) ; v1(65.43,64.69) 65.43,64.16 v1(65.38,64.11) ; v1(65.43,64.69) v1(65.94,64.69) ; v1(56.08,65.15) 56.2,65.27 U1.29 ; v1(65.38,64.11) 65.22,64.27 U1.6 ; v1(65.38,64.11) 65.94,63.55 v1(65.94,63.53) ; U1.30 56.31,64.77 v1(56.08,64.54) ; v1(56.34,68.22) 56.13,68.02 v1(56.13,67.59) 56.46,67.27 U1.25 ; U1.12 65.08,67.27 v1(65.41,67.59) 65.41,67.69 v1(64.85,68.25)
  BOTTOM w0.508: v1(56.01,65.74) 56.08,65.66 56.08,65.53 ; v1(65.41,67.59) 65.33,67.67 C36.1 v1(64.85,68.25) ; 56.34,67.31 56.34,67.11 C31.1 C32.1 56.74,67.82 v1(56.34,68.22) ; 56.34,67.31 v1(56.34,68.22) ; 56.34,67.31 56.13,67.31 v1(56.13,67.59) 56.13,68.02 v1(56.34,68.22) ; 56.77,64.95 C30.1 56.21,65.53 ; 56.77,64.95 C29.1 ; 56.77,64.95 56.21,64.95 56.21,65.53 ; 56.77,64.95 C29.1 ; 64.9,64.72 C37.1 v1(65.41,65.23) C33.1 v1(65.94,64.69) ; 64.9,64.72 65.41,64.72 v1(65.43,64.69) v1(65.94,64.69) ; 64.9,64.72 C170.1 v1(65.38,64.11) C169.1 ; v1(65.94,64.69) C169.1 ; 56.21,65.53 56.08,65.53 ; 56.08,65.53 v1(56.08,65.15) v1(56.08,64.54) 56.24,64.39 C29.1 ; C169.1 v1(65.94,63.53) ; C35.1 C34.1 v1(60.07,69.11) v1(61.47,69.11) C35.1
  vias: v1(41.68,54.46) v1(41.68,53.82) v1(42.32,54.46) v1(42.32,53.82) v1(42.98,52.17) v1(43,54.48) v1(43,53.7) v1(43,52.93) v1(43.64,54.46) v1(43.64,53.7) v1(43.64,52.93) v1(43.61,52.17) v1(44.32,54.46) v1(44.32,53.7) v1(44.32,52.93) v1(44.3,52.17)
DVDD1.8V: length 25.6
  TOP w0.305: v1(65.51,62.79) 65.03,63.27 U1.4 ; v1(56.18,63.02) 56.43,63.27 U1.33 ; U1.35 v1(56.2,62.27) ; U1.2 65.19,62.27 v1(65.46,62)
  TOP w0.508: JP1.1 95.86,49.3 v1(95.86,37.06)
  BOTTOM w0.305: R57.1 v1(95.86,37.06)
  BOTTOM w0.508: R87.1 v1(105.05,55.73) ; v1(56.44,61.37) 56.77,61.7 C39.1 56.36,62.1 v1(56.2,62.27) ; C38.1 56.41,63.25 v1(56.18,63.02) ; v1(64.9,61.14) C40.1 65.3,61.85 v1(65.46,62) ; v1(65.51,62.79) 65.3,62.99 C41.1
  vias: v1(41.73,45.9) v1(42.37,45.9) v1(42.77,46.33) v1(42.9,48.21) v1(42.93,47.6) v1(42.9,46.96) v1(43.15,45.9) v1(43.56,48.21) v1(43.59,47.62) v1(43.56,46.99) v1(43.64,46.36) v1(43.97,45.87) v1(44.27,48.18) v1(44.27,46.99) v1(44.27,46.36) v1(44.3,47.62)
GND: length 224.5
  TOP w0.305: J13.104 v1(47.31,10.75) ; J13.103 v1(47.31,2.29) ; J13.79 v1(53.32,2.29) ; v1(58.75,63.5) 58.48,63.77 U1.32 ; J13.80 v1(53.32,10.72) ; J13.17 v1(73.82,2.23) ; U1.36 57.27,61.78 57.84,61.78 58.29,62.23 58.5,62.23 v1(58.75,62.48) 58.47,62.77 U1.34 ; 22.82,46.99 v2(22.98,46.99) 23.08,47.09 U5.10 ; J13.36 v1(69.32,10.87) ; J13.86 v1(51.82,10.79) ; U1.5 63.08,63.77 v1(62.81,63.5) ; J13.47 v1(66.31,2.26) ; J13.42 v1(67.82,10.82) ; J13.59 v1(63.31,2.3) ; v3(34.63,27.07) 34.63,28.62 v1(34.54,28.7) ; J13.73 v1(54.82,2.27) ; J13.30 v1(70.82,10.82) ; J13.110 v1(45.81,10.81) ; v3(34.62,26.2) 34.65,26.17 U4.2 35.81,26.17 v1(36.07,25.91) ; J13.54 v1(64.81,10.76) ; J13.24 v1(72.32,10.82) ; J13.98 v1(48.81,10.79) ; v1(13.87,55.7) 13.88,55.69 U8.7 15.8,55.69 v2(15.85,55.74) ; U1.1 64.29,61.78 63.7,61.78 63.25,62.23 63.07,62.23 v1(62.81,62.48) 63.1,62.77 U1.3 ; J13.116 v1(44.31,10.83) ; J13.48 v1(66.31,10.82) ; J13.61 v1(57.82,2.3) ; J13.68 v1(56.32,10.69) ; J13.109 v1(45.81,2.25) ; J13.11 v1(75.32,2.27) ; v2(25.08,46.99) 25.03,47.04 U5.7 ; J13.6 v1(76.82,10.86) ; J13.92 v1(50.31,10.74) ; J13.18 v1(73.82,10.78) ; J13.67 v1(56.32,2.3) ; J13.35 v1(69.32,2.29) ; J13.12 v1(75.32,10.84) ; J13.23 v1(72.32,2.31) ; J13.41 v1(67.82,2.28) ; 25.78,47.02 v2(25.78,46.99) ; J13.29 v1(70.82,2.26) ; J13.5 v1(76.82,2.25) ; J13.97 v1(48.81,2.24) ; J13.60 v1(63.31,10.73) ; J13.91 v1(50.31,2.26) ; J13.74 v1(54.82,10.69) ; J13.62 v1(57.82,10.73) ; J13.53 v1(64.81,2.25) ; J13.85 v1(51.82,2.24)
  TOP w0.483: R7.2 v1(103.68,70.03) ; R11.2 v1(103.68,62.92)
  TOP w0.508: C56.1 v1(23.72,15.77) C55.2 ; C56.1 v1(26.77,15.77) ; C56.1 v1(25.27,14.99) ; R118.1 v1(11.23,55.68) ; U2.18 v1(104.64,43.95) ; J14.9 v1(120.98,35) ; J14.9 v1(117.93,35) ; J14.9 v1(119.47,33.69) ; J14.9 v1(119.47,36.41) ; v1(25.02,39.37) C69.2 v1(25.65,38.86) ; C54.2 v1(105.54,46.61) ; C190.1 v1(23.24,50.8) ; v2(15.85,53.64) 15.82,53.64 v1(14.78,52.6) ; v1(112.29,41.05) J14.5 v1(115.37,41.05) ; D1.2 v1(21.97,33.15) ; D1.2 v1(22.99,32.26) ; D1.2 v1(20.96,32.26) ; C197.2 v1(19.53,47.65) ; C49.2 v1(99.31,46.61) ; v1(28.45,37.82) C73.2 v1(27.56,38.61) ; C55.2 v1(20.73,15.77) ; C55.2 v1(22.23,14.99) ; v1(65.66,74.24) 65.3,73.89 C45.2 ; J14.7 v1(113.97,42.6) ; J14.7 v1(112.31,43.9) ; J14.7 v1(113.97,45.29) ; J14.7 v1(115.52,43.9) ; C191.1 v1(23.77,52.78) ; C196.1 v1(22.05,61.72) ; v1(35.05,23.62) C60.1 v1(34.54,24.13) ; R81.2 v1(37.97,27.94) ; J14.6 v1(119.47,45.25) ; J14.6 v1(120.99,43.9) ; J14.6 v1(119.47,42.58) ; J14.6 v1(117.9,43.9) ; C61.2 v1(34.42,22.78) ; C61.2 v1(34.42,20.98) ; C61.2 v1(35.18,21.84) ; C3.1 v1(77.6,66.42) ; v1(54.25,74.22) 54.64,73.84 C48.2 ; v1(24,24.28) C57.2 v1(24,26.04) ; R63.2 v1(46.6,80.5) ; R119.1 v1(11.23,56.95) ; v1(15.62,45.97) C68.1 v1(15.11,45.34) ; v1(46.56,65.63) C11.1 ; R65.2 v1(47.98,81.85) ; C63.1 v1(35.56,31.5) ; C63.1 v1(34.77,32.99) ; C63.1 v1(34.77,30) ; v1(18.41,28.96) U3.2 v1(18.41,30.99) ; U9.2 v1(24.87,58.39) ; R20.2 v1(18.03,63.01) ; v2(15.85,56.44) 15.36,56.93 ; v1(24.49,27.41) C58.2 v1(23.88,26.8) ; R115.2 v1(24.79,60.1) ; C194.2 v1(20.85,61.72) ; U2.26 v1(99.44,43.94) ; v1(27.43,32.77) FB3.2 v1(27.43,30.23) ; v1(26.92,38.3) C71.2 v1(26.26,38.96) ; J14.8 v1(113.97,33.71) ; J14.8 v1(113.97,36.4) ; J14.8 v1(112.34,35) ; J14.8 v1(115.51,35) ; v1(14.86,44.7) C67.2 v1(14.1,43.81) ; U2.25 v1(100.09,41.16) ; v1(64.41,70.36) 65.43,70.36 ; v1(18.29,46.48) C70.1 v1(17.78,46.99) ; C10.1 v1(43.92,66.55) ; R117.1 v1(11.25,54.41) ; R80.2 v1(36.7,25.91) ; R114.1 v1(16.51,48.49) ; R113.1 v1(15.24,48.49) ; C59.1 v1(24.38,28.07) ; R59.2 v1(71.86,82) ; C52.2 v1(109.42,41.27) ; C192.2 v1(16.36,61.65) ; v2(18.65,53.64) 19.3,52.98 ; R86.2 v1(109.47,43.41) ; R82.2 v1(35.18,29.08) ; C50.2 v1(101.85,45.09) ; C4.1 v1(74.99,65.6) ; R25.2 v1(17.91,70.13) ; R116.1 v1(11.3,53.14) ; R62.2 v1(73.38,80.47) ; U2.21 v1(102.69,44.01) ; C195.2 v1(17.78,47.73) ; C198.1 v1(23.93,61.19) ; C51.2 v1(100.33,46.86) ; C53.2 v1(109.4,36.91) ; C62.1 v1(34.54,28.7) ; C193.2 v1(15.85,60.02) ; U2.7 v1(102.04,37.28)
  BOTTOM w0.305: U7.15 95.36,78.54 v1(95.38,78.56) ; U10.13 25.58,73.25 v1(25.78,73.05) ; U10.16 24.08,73.26 v1(23.88,73.05) ; U7.13 94.36,78.53 v1(94.36,78.54) ; v1(95.91,78.99) 95.86,78.94 U7.16 ; U7.14 94.86,79.01 v1(94.87,79.02) ; v1(24.43,72.77) 24.43,72.79 24.58,72.94 U10.15 ; U10.14 25.08,72.89 25.2,72.77 25.22,72.77 v1(25.23,72.76)
  BOTTOM w0.483: C210.G1 22.83,80.04 ; R157.2 v1(80.9,75.62) ; C210.G2 22.84,78.61 22.84,78.47 ; 22.26,71.23 v1(22.28,71.25) ; R155.2 v1(39.01,75.59) ; C207.2 v1(99.49,71.81)
  BOTTOM w0.508: C188.1 v1(95.94,81.53) ; SJP2.1 v1(13.82,80.7) ; SJP2.1 v1(14.63,81.48) ; SJP2.1 v1(14.63,79.96) ; C39.2 58.37,62.1 v1(58.75,62.48) ; R85.1 22.73,47.24 v2(22.98,46.99) ; R108.1 v1(94.79,81.51) ; 58.72,66.67 58.72,67.34 58.42,67.64 57.96,67.64 C32.2 ; 58.72,66.67 C31.2 ; 58.72,66.67 58.72,66.57 v1(58.75,66.55) ; D2.3 v1(11.18,52.2) ; D2.3 v1(11.18,48.54) ; D2.3 v1(11.98,50.36) ; D2.3 v1(10.38,50.36) ; C29.2 58.62,64.39 v1(58.75,64.52) ; C173.2 70.44,76.48 v1(70.76,76.16) ; C38.2 58.5,63.25 v1(58.75,63.5) ; v1(33.68,68.73) 33.7,68.71 C13.1 ; C74.2 22.96,44.86 v2(22.99,44.88) ; C12.1 23.64,68.7 v1(23.65,68.71) ; R124.1 31.55,72.34 v1(31.6,72.39) ; v1(62.81,66.55) 63.83,67.56 C36.2 ; D4.1 22.26,71.23 ; 6.1,50.36 v1(6.1,52.17) ; 6.1,50.36 v1(5.3,50.36) ; 6.1,50.36 v1(6.85,50.36) ; 6.1,50.36 v1(6.1,48.62) ; C35.2 61.47,66.88 v1(61.8,66.55) ; C209.2 v1(91.34,71.48) ; C66.1 v1(29.97,36.6) ; R151.2 v1(90.12,71.96) ; 97.92,68.33 v1(97.92,68.88) ; C189.2 v1(28.63,79.88) ; C37.2 63.12,65.23 v1(62.81,65.53) ; v2(22.99,46.3) 22.78,46.1 R84.1 ; R58.2 v1(101.63,55.6) ; C64.2 v1(21.06,39.78) ; C200.1 31.57,73.56 v1(31.6,73.53) ; C72.1 v1(32.77,36.6) ; v1(103.84,79.68) R98.2 ; SJP1.1 v1(105.46,73.2) ; v1(62.81,64.52) 63.22,64.11 C170.2 ; C160.G1 v1(96.95,73.53) ; C34.2 60.07,66.85 v1(59.77,66.55) ; C41.2 63.32,62.99 v1(62.81,63.5) ; R96.2 v1(102.69,73.58) ; C42.2 v1(55.6,69.27) ; C6.1 v1(87.88,68.76) ; C40.2 63.45,61.85 v1(62.81,62.48) ; 22.84,78.47 v1(22.84,78.02) ; 19,82.3 v1(18.36,82.3) ; 22.83,80.04 v1(22.83,80.44) ; D3.1 98.31,82.18 v1(98.3,82.19) ; C199.2 24.84,81.15 v1(24.43,81.15) ; C174.2 v1(52.51,79.41) ; C160.G2 v1(96.95,71.5) ; C187.2 v1(89.08,77.9) ; R131.2 v1(17.3,79.25) ; C30.2 v1(58.75,65.53) ; v1(66.95,63.55) C169.2 ; R133.2 v1(16.1,72.85) ; v1(66.95,65.61) C33.2 ; C65.1 v1(19.05,39.88) ; R153.2 v1(29.87,79.04) ; v1(33.96,37.21) U6.2 v1(35.97,37.21) ; R83.2 v1(39.98,36.7) ; C168.2 v1(102.13,56.87)
  vias: v1(0.48,79.53) v1(0.48,73.33) v1(0.48,60.02) v1(0.56,96.65) v1(0.51,93.65) v1(0.51,90.2) v1(0.51,85.98) v1(0.51,82.17) v1(0.53,75.84) v1(0.51,68.2) v1(0.51,65.66) v1(0.51,63.12) v1(0.51,57.48) v1(0.51,52.45) v1(0.51,48.64) v1(0.51,44.83) v1(0.51,41.02) v1(0.51,37.21) v1(0.51,33.4) v1(0.51,29.59) v1(0.51,25.78) v1(0.51,22.99) v1(0.51,20.19) v1(1.85,60.02) v1(1.93,75.87) v1(1.96,73.33) v1(1.93,57.48) v1(2.54,50.8) v1(2.54,45.72) v1(3.15,60.02) v1(3.25,75.87) v1(3.33,57.48) v1(3.56,96.7) v1(3.56,73.36) v1(3.51,66.55) v1(3.51,64.08) v1(3.63,69.29) v1(3.78,94.08) v1(4.27,59.99) v1(4.57,53.16) v1(4.98,57.73) v1(5.08,81.28) v1(5.03,75.62) v1(5.08,73.86) v1(5.11,59.49) v1(5.26,44.2) v1(6.35,75.64) v1(6.3,73.89) v1(6.38,57.68) v1(6.63,70.18) v1(6.76,77.95) v1(6.83,66.5) v1(6.83,63.17) v1(6.81,59.46) v1(7.29,96.7) v1(7.32,73.36) v1(7.52,75.62) v1(7.62,93.98) v1(7.62,57.81) v1(7.62,45.72) v1(7.75,13.21) v1(7.8,60.5) v1(7.95,54.46) v1(8.26,72.42) v1(8.38,83.74) v1(8.51,74.68) v1(8.61,58.83) v1(8.84,61.54) v1(9.5,73.66) v1(9.53,59.72) v1(9.6,75.74) v1(9.75,70.94) v1(9.75,62.46) v1(10.16,91.44) v1(10.16,81.28) v1(10.29,88.72) v1(10.36,60.55) v1(10.46,72.67) v1(10.44,66.55) v1(10.44,44.2) v1(10.67,96.72) v1(10.69,70) v1(10.74,63.42) v1(11.1,61.29) v1(11.51,71.68) v1(11.56,13.21) v1(11.63,69.06) v1(11.61,64.26) v1(11.91,16.81) v1(12.17,62.38) v1(12.34,70.82) v1(12.52,65.1) v1(12.62,68.12) v1(12.7,93.98) v1(12.7,83.82) v1(12.7,45.72) v1(13.06,75.31) v1(13.03,73.96) v1(13.13,72.39) v1(13.11,63.32) v1(13.34,69.88) v1(13.82,88.72) v1(13.87,76.38) v1(13.87,71.65) v1(13.82,58.5) v1(14.07,68.15) v1(14.02,65.07) v1(14.05,63.32) v1(14.38,91.72) v1(14.48,96.72) v1(14.68,70.82) v1(14.86,73.23) v1(14.96,76.94) v1(14.94,35.41) v1(15.06,74.98) v1(15.09,74.14) v1(15.06,42.19) v1(15.01,38.63) v1(15.19,69.88) v1(15.21,79.5) v1(15.27,63.32) v1(15.24,15.24) v1(15.32,85.57) v1(15.34,78.21) v1(15.37,13.21) v1(15.52,68.12) v1(15.6,65.1) v1(15.82,72.34) v1(15.95,66.62) v1(16.36,76) v1(16.38,62.94) v1(16.41,76.86) v1(16.48,75.26) v1(16.74,71.35) v1(16.94,73.51) v1(17.27,68.07) v1(17.3,65.1) v1(17.55,76.86) v1(17.6,75.26) v1(17.78,93.98) v1(17.78,88.9) v1(18.14,73.51) v1(18.29,96.72) v1(18.49,78.59) v1(18.47,76.83) v1(18.49,16.97) v1(18.67,75.23) v1(18.67,66.04) v1(18.75,79.83) v1(19.02,62.76) v1(19.18,13.21) v1(19.2,70) v1(19.23,68.25) v1(19.2,64.95) v1(19.35,73.46) v1(19.38,67.06) v1(19.48,76.63) v1(19.56,78.49) v1(19.53,75.46) v1(19.81,51.69) v1(19.99,76.1) v1(20.32,91.44) v1(20.32,86.36) v1(20.5,35.26) v1(20.7,78.49) v1(20.7,70.43) v1(21.23,62.59) v1(21.62,73.74) v1(21.97,70.43) v1(22.1,96.72) v1(22.25,77.62) v1(22.38,62.59) v1(22.61,13.21) v1(22.71,73.79) v1(22.86,93.98) v1(22.86,88.9) v1(23.06,49.05) v1(23.01,40.82) v1(23.09,27.97) v1(23.11,76.83) v1(23.37,30.2) v1(23.37,11.05) v1(23.37,8.25) v1(23.37,5.46) v1(23.37,2.92) v1(23.37,0.51) v1(23.42,70.43) v1(23.65,64.24) v1(23.9,38.99) v1(23.98,21.92) v1(24.23,41.91) v1(24.37,75.77) v1(24.37,74.85) v1(24.79,62.61) v1(24.89,86.46) v1(24.83,75.31) v1(24.94,70.43) v1(25.02,49.02) v1(25.29,75.77) v1(25.29,74.85) v1(25.43,91.49) v1(25.4,10.16) v1(25.4,5.08) v1(25.5,37.41) v1(25.91,96.72) v1(26.11,62.61) v1(26.14,50.83) v1(26.29,76.83) v1(26.24,73.81) v1(26.34,70.46) v1(26.64,67.64) v1(26.64,65.38) v1(26.67,60.6) v1(27.03,89.13) v1(27.18,0.51) v1(27.23,77.57) v1(27.28,73.74) v1(27.48,72.52) v1(27.48,26.57) v1(27.48,24.56) v1(27.53,62.59) v1(27.56,21.87) v1(27.61,70.46) v1(27.61,56.64) v1(27.74,67.64) v1(27.79,65.35) v1(27.86,48.69) v1(27.94,93.98) v1(27.94,17.78) v1(27.94,12.7) v1(27.94,7.62) v1(27.94,2.54) v1(28.52,86.36) v1(28.52,82.47) v1(29.03,46.76) v1(29.26,50.75) v1(29.36,65.33) v1(29.34,62.66) v1(29.59,67.61) v1(29.72,96.72) v1(29.82,24.26) v1(29.9,70.46) v1(29.97,54.86) v1(30.48,91.44) v1(30.48,53.34) v1(30.48,20.32) v1(30.48,15.24) v1(30.48,10.16) v1(30.48,5.08) v1(30.78,67.67) v1(30.78,65.38) v1(30.73,56.57) v1(30.81,62.61) v1(30.94,44.68) v1(30.99,0.51) v1(31.14,70.48) v1(31.39,60.5) v1(31.67,48.74) v1(32.16,86.33) v1(32.18,74.09) v1(32.21,62.61) v1(32.39,70.46) v1(32.56,82.47) v1(33.02,93.98) v1(33.02,88.9) v1(33.02,50.8) v1(33.07,17.73) v1(33.02,12.7) v1(33.02,7.62) v1(33.02,2.54) v1(33.27,74.3) v1(33.53,96.72) v1(33.73,64.26) v1(33.71,54.25) v1(33.73,46.71) v1(33.99,70.43) v1(34.06,44.6) v1(34.19,35.38) v1(34.37,62.64) v1(34.67,43.71) v1(34.7,74.14) v1(34.7,72.9) v1(34.8,76.99) v1(34.8,0.51) v1(35.18,60.48) v1(35.43,58.45) v1(35.56,91.44) v1(35.53,86.64) v1(35.56,20.32) v1(35.56,15.24) v1(35.56,10.16) v1(35.64,70.46) v1(35.64,42.27) v1(35.84,62.61) v1(35.81,21.84) v1(35.94,22.86) v1(36.32,78) v1(36.32,73.18) v1(36.86,33.96) v1(37.01,70.48) v1(37.19,67.67) v1(37.24,62.61) v1(37.34,96.72) v1(37.49,74.73) v1(37.49,73.33) v1(37.44,65.41) v1(37.44,22.89) v1(37.59,77.85) v1(37.95,76.43) v1(38.1,93.98) v1(38.1,88.9) v1(38.18,69.95) v1(38.18,68.22) v1(38.18,63.04) v1(38.1,55.88) v1(38.1,17.78) v1(38.1,12.7) v1(38.1,7.62) v1(38.1,2.54) v1(38.3,60.4) v1(38.43,64.82) v1(38.61,0.51) v1(38.71,73.48) v1(39.19,66.45) v1(39.24,82.09) v1(39.27,80.34) v1(39.34,70.15) v1(39.37,25.53) v1(39.42,68) v1(39.45,62.89) v1(39.6,65) v1(39.88,72.21) v1(39.93,76.53) v1(39.93,74.73) v1(40.34,82.09) v1(40.39,80.34) v1(40.54,70.15) v1(40.64,91.44) v1(40.61,68.02) v1(40.61,62.86) v1(40.64,58.42) v1(40.64,50.8) v1(40.64,30.48) v1(40.64,25.4) v1(40.64,20.32) v1(40.64,15.24) v1(40.64,10.16) v1(40.77,86.64) v1(40.84,65.02) v1(41.15,96.72) v1(41.12,73.89) v1(41.15,6.48) v1(41.27,76.25) v1(41.3,66.45) v1(41.88,82.09) v1(41.88,80.37) v1(41.86,69.95) v1(41.81,63.04) v1(42.06,78.41) v1(42.01,72.95) v1(42.12,6.48) v1(42.29,75.26) v1(42.24,68.22) v1(42.21,64.82) v1(42.42,0.51) v1(42.62,77.19) v1(42.95,72.03) v1(42.9,70.1) v1(42.95,62.84) v1(43.05,6.48) v1(43.18,93.98) v1(43.18,88.9) v1(43.18,55.88) v1(43.18,43.18) v1(43.13,37.82) v1(43.18,33.02) v1(43.18,27.94) v1(43.18,22.86) v1(43.18,17.78) v1(43.18,12.7) v1(43.18,7.62) v1(43.28,80.37) v1(43.31,82.07) v1(43.38,60.4) v1(43.43,74.12) v1(43.76,71.2) v1(43.97,79.43) v1(43.99,70.05) v1(44.27,62.89) v1(44.42,81.69) v1(44.45,73.1) v1(44.78,84.48) v1(44.73,78.66) v1(44.86,76.02) v1(44.96,96.72) v1(45.36,81) v1(45.34,77.52) v1(45.31,6.5) v1(45.42,72.16) v1(45.42,62.92) v1(45.59,70.97) v1(45.72,91.44) v1(45.72,58.42) v1(45.72,50.8) v1(45.72,45.72) v1(45.72,40.64) v1(45.72,35.56) v1(45.72,30.48) v1(45.72,25.4) v1(45.72,20.32) v1(45.72,15.24) v1(45.85,52.32) v1(46.05,76.83) v1(46.23,0.51) v1(46.35,6.5) v1(46.48,70.1) v1(46.58,67.61) v1(46.71,62.86) v1(46.89,76.02) v1(47.39,6.48) v1(47.47,84.25) v1(47.55,82.98) v1(47.62,85.47) v1(47.78,70.13) v1(47.8,80.59) v1(47.93,62.86) v1(48.26,48.26) v1(48.26,43.18) v1(48.29,37.92) v1(48.26,33.02) v1(48.26,27.94) v1(48.26,22.86) v1(48.26,17.78) v1(48.26,5.08) v1(48.46,60.4) v1(48.46,6.5) v1(48.54,86.39) v1(48.77,96.72) v1(49.02,73.84) v1(49.02,70.13) v1(49.17,84.53) v1(49.17,76.07) v1(49.3,88.82) v1(49.3,87.17) v1(49.3,62.89) v1(49.4,6.5) v1(49.78,56.01) v1(49.81,83.69) v1(49.94,72.95) v1(50.06,85.45) v1(50.04,0.51) v1(50.22,94.13) v1(50.37,70.08) v1(50.57,62.94) v1(50.77,83.21) v1(50.8,72.09) v1(50.88,65.2) v1(50.8,58.42) v1(50.8,53.34) v1(50.8,45.72) v1(50.8,40.64) v1(50.8,35.56) v1(50.8,30.48) v1(50.8,25.4) v1(50.8,20.32) v1(50.8,15.24) v1(50.8,7.62) v1(50.9,86.33) v1(50.95,67.77) v1(51,88.8) v1(51,87.68) v1(51.54,82.45) v1(51.66,71.35) v1(51.71,70.08) v1(51.77,62.94) v1(51.71,6.5) v1(52.32,81.66) v1(52.45,73.05) v1(52.58,96.72) v1(52.55,70.48) v1(52.78,69.67) v1(52.76,63.14) v1(52.76,6.5) v1(52.81,64.06) v1(53.06,60.96) v1(53.09,52.73) v1(53.06,51.28) v1(53.09,47.47) v1(53.06,45.64) v1(53.09,43.89) v1(53.09,42.09) v1(53.09,40.16) v1(53.04,38.61) v1(53.09,31.22) v1(53.09,29.29) v1(53.09,27.25) v1(53.09,19.68) v1(53.09,18.01) v1(53.09,16.41) v1(53.09,14.43) v1(53.06,13) v1(53.11,54.36) v1(53.11,49.63) v1(53.14,36.45) v1(53.16,34.75) v1(53.11,32.74) v1(53.11,25.27) v1(53.11,23.47) v1(53.11,21.56) v1(53.29,68.86) v1(53.24,55.93) v1(53.34,5.08) v1(53.52,71.96) v1(53.77,74.7) v1(53.75,70.21) v1(53.74,6.48) v1(53.82,59.16) v1(53.85,0.51) v1(53.92,80.95) v1(53.92,67.44) v1(53.9,64.36) v1(54.38,57.05) v1(54.56,65.58) v1(54.69,72.44) v1(54.79,22.17) v1(54.76,20.37) v1(54.79,18.49) v1(54.79,15.06) v1(54.76,13.03) v1(54.84,79.1) v1(54.86,64.36) v1(54.89,51.36) v1(54.81,23.95) v1(54.81,16.71) v1(54.81,6.5) v1(54.91,54.99) v1(54.94,53.14) v1(54.97,49.45) v1(54.94,47.09) v1(54.94,45.49) v1(54.99,43.15) v1(54.91,40.74) v1(54.97,36.37) v1(54.94,33.99) v1(54.94,29.26) v1(54.91,26.77) v1(55.04,38.58) v1(55.02,31.75) v1(55.32,75.92) v1(55.32,69.93) v1(55.3,67.46) v1(55.52,58.19) v1(55.68,61.67) v1(55.7,78.26) v1(55.78,36.78) v1(55.75,32.92) v1(55.78,6.5) v1(55.88,93.98) v1(55.88,88.9) v1(55.88,83.82) v1(55.8,54.15) v1(55.8,52.2) v1(55.83,46.33) v1(55.83,44.27) v1(55.8,41.99) v1(55.8,39.78) v1(55.83,35.13) v1(55.8,30.4) v1(55.83,28.35) v1(55.83,25.15) v1(55.88,7.62) v1(56.03,73.79) v1(56.11,56.49) v1(56.21,50.24) v1(56.24,48.13) v1(56.29,20.42) v1(56.29,14.73) v1(56.29,13) v1(56.39,96.72) v1(56.36,74.96) v1(56.39,21.97) v1(56.34,18.64) v1(56.36,16.74) v1(56.41,70.74) v1(56.46,23.22) v1(56.57,77.14) v1(56.57,59.26) v1(57.12,70.03) v1(57.15,60.78) v1(57.38,57.71) v1(57.4,76.3) v1(57.63,55.65) v1(57.63,54.18) v1(57.63,52.55) v1(57.63,51.38) v1(57.66,46.99) v1(57.63,45.92) v1(57.68,44.37) v1(57.68,42.42) v1(57.63,39.93) v1(57.68,36.68) v1(57.61,33.63) v1(57.63,31.04) v1(57.63,28.7) v1(57.66,26.31) v1(57.66,24.61) v1(57.66,0.51) v1(57.73,72.09) v1(57.96,21.03) v1(57.99,19.3) v1(57.96,17.98) v1(57.99,14.38) v1(57.99,12.98) v1(58.04,49.5) v1(58.06,47.6) v1(58.01,15.98) v1(58.01,6.48) v1(58.12,75.26) v1(58.12,74.04) v1(58.17,51.97) v1(58.17,50.55) v1(58.42,91.44) v1(58.42,86.36) v1(58.42,81.28) v1(58.42,73.1) v1(58.45,58.78) v1(58.45,53.47) v1(58.47,41.3) v1(58.45,38.61) v1(58.42,5.08) v1(58.52,71.27) v1(58.52,56.52) v1(58.5,54.81) v1(58.52,48.56) v1(58.5,45.52) v1(58.52,43.41) v1(58.5,35.2) v1(58.52,32.69) v1(58.5,30.18) v1(58.52,27.86) v1(58.55,25.83) v1(58.5,24.16) v1(59.01,6.48) v1(59.18,22.25) v1(59.39,70.36) v1(59.77,65.53) v1(59.77,64.52) v1(59.77,63.5) v1(59.77,62.48) v1(59.99,52.45) v1(59.99,51.18) v1(59.99,46.61) v1(59.97,6.5) v1(60.2,96.72) v1(60.33,54.2) v1(60.33,49.68) v1(60.35,48.01) v1(60.35,45.11) v1(60.33,42.8) v1(60.33,36.75) v1(60.33,34.92) v1(60.33,32.51) v1(60.35,30.1) v1(60.35,28.04) v1(60.35,26.57) v1(60.33,25.43) v1(60.33,23.6) v1(60.4,40.31) v1(60.48,19.56) v1(60.58,15.04) v1(60.53,10.82) v1(60.68,56.85) v1(60.78,66.55) v1(60.78,65.53) v1(60.78,64.52) v1(60.78,63.5) v1(60.78,62.48) v1(60.88,70.84) v1(60.83,51.87) v1(60.96,93.98) v1(60.96,88.9) v1(60.96,83.82) v1(60.96,78.74) v1(60.96,47.45) v1(60.96,7.62) v1(60.96,2.54) v1(61.06,55.32) v1(61.09,43.99) v1(61.09,38.91) v1(61.09,35.86) v1(61.06,33.78) v1(61.14,53.37) v1(61.11,41.73) v1(61.16,31.24) v1(61.11,28.98) v1(61.11,27.38) v1(61.11,26.14) v1(61.14,24.08) v1(61.14,6.48) v1(61.21,50.17) v1(61.21,49.25) v1(61.42,73.23) v1(61.42,45.87) v1(61.47,0.51) v1(61.59,71.48) v1(61.87,74.07) v1(61.8,65.53) v1(61.8,64.52) v1(61.8,63.5) v1(61.8,62.48) v1(61.95,22.66) v1(62,75.36) v1(62.13,6.48) v1(62.2,69.72) v1(62.31,72.06) v1(62.61,51.36) v1(62.81,76.17) v1(62.89,56.46) v1(62.84,48.36) v1(62.81,47.07) v1(62.94,70.28) v1(62.92,54.61) v1(62.92,52.73) v1(62.92,44.3) v1(62.92,42.21) v1(62.97,39.22) v1(62.94,36.07) v1(62.97,33.43) v1(62.97,29.92) v1(62.94,27.13) v1(62.94,24.33) v1(63.07,58.47) v1(63.02,49.71) v1(63.09,14.66) v1(63.07,6.5) v1(63.14,21.46) v1(63.14,19.61) v1(63.17,17.98) v1(63.12,16.33) v1(63.17,13.06) v1(63.22,45.97) v1(63.5,91.44) v1(63.5,86.36) v1(63.5,81.28) v1(63.58,76.96) v1(63.58,70.82) v1(63.58,53.64) v1(63.58,36.75) v1(63.58,31.24) v1(63.58,28.47) v1(63.5,5.08) v1(63.63,55.58) v1(63.63,52.02) v1(63.63,47.45) v1(63.63,44.96) v1(63.63,43.31) v1(63.63,40.79) v1(63.65,34.47) v1(63.63,25.83) v1(63.91,78.03) v1(63.91,73.81) v1(64.01,96.72) v1(64.06,75.01) v1(64.08,50.24) v1(64.11,57.45) v1(64.13,48.62) v1(64.54,59.31) v1(64.67,23.55) v1(64.82,75.77) v1(64.82,22.05) v1(64.82,19.94) v1(64.82,18.29) v1(64.8,16.59) v1(64.82,14.76) v1(64.82,12.98) v1(64.97,79.07) v1(65.18,56.44) v1(65.25,72.52) v1(65.28,0.51) v1(65.33,6.5) v1(65.48,54.33) v1(65.48,52.81) v1(65.46,51.46) v1(65.41,47.37) v1(65.46,45.67) v1(65.46,43.64) v1(65.48,41.61) v1(65.41,38.58) v1(65.46,35.71) v1(65.46,32.92) v1(65.46,27.84) v1(65.46,25.43) v1(65.51,30.07) v1(65.66,58.27) v1(65.74,61.14) v1(65.86,50.11) v1(65.94,70.43) v1(65.94,48.84) v1(66.04,83.82) v1(66.04,7.62) v1(66.14,74.73) v1(66.17,67.44) v1(66.27,62.31) v1(66.29,59.59) v1(66.34,54.97) v1(66.37,53.21) v1(66.37,51.99) v1(66.37,50.8) v1(66.37,46.51) v1(66.34,40) v1(66.34,36.78) v1(66.34,28.98) v1(66.37,26.82) v1(66.34,6.5) v1(66.42,72.16) v1(66.4,49.53) v1(66.42,48.01) v1(66.4,44.75) v1(66.4,42.75) v1(66.4,34.34) v1(66.4,31.6) v1(66.42,24.38) v1(66.47,22.28) v1(66.45,20.12) v1(66.47,18.29) v1(66.45,16.59) v1(66.45,14.68) v1(66.42,13) v1(66.78,57.12) v1(67.31,70.56) v1(67.49,81.61) v1(67.41,73.18) v1(67.4,6.48) v1(67.51,79.35) v1(67.51,56.41) v1(67.61,67.46) v1(67.82,96.72) v1(68.17,71.5) v1(68.25,55.52) v1(68.25,53.29) v1(68.22,51.41) v1(68.22,49.96) v1(68.22,48.23) v1(68.25,46.51) v1(68.22,44.88) v1(68.2,43.1) v1(68.22,41.27) v1(68.2,39.7) v1(68.22,34.04) v1(68.22,32.28) v1(68.22,30.56) v1(68.22,28.85) v1(68.22,26.87) v1(68.25,24.87) v1(68.22,22.91) v1(68.22,20.8) v1(68.2,18.69) v1(68.22,16.81) v1(68.2,14.91) v1(68.2,13.08) v1(68.35,88.82) v1(68.35,87.5) v1(68.35,82.5) v1(68.33,35.66) v1(68.43,69.29) v1(68.45,38.07) v1(68.45,6.48) v1(68.58,5.08) v1(68.91,86.46) v1(69.09,0.51) v1(69.14,83.24) v1(69.19,72.19) v1(69.24,93.98) v1(69.42,6.5) v1(69.72,70.08) v1(69.72,62.92) v1(69.85,85.5) v1(70.05,88.8) v1(70.08,87.68) v1(70.08,83.79) v1(70.03,73.03) v1(70.05,59.79) v1(70.66,67.79) v1(70.69,65.2) v1(70.74,84.61) v1(70.99,86.82) v1(70.92,73.89) v1(71.12,70.08) v1(71.12,62.92) v1(71.12,48.26) v1(71.12,43.18) v1(71.12,38.1) v1(71.12,27.94) v1(71.12,22.86) v1(71.12,17.78) v1(71.12,7.62) v1(71.22,32.72) v1(71.63,96.72) v1(71.7,6.5) v1(71.81,85.98) v1(71.93,58.39) v1(72.11,80.7) v1(72.11,75.01) v1(72.29,82.98) v1(72.42,85.09) v1(72.47,62.92) v1(72.57,70.03) v1(72.75,6.48) v1(72.82,83.95) v1(72.9,0.51) v1(73.1,76.05) v1(73.15,53.34) v1(73.66,91.44) v1(73.63,62.86) v1(73.66,45.72) v1(73.66,40.64) v1(73.66,35.56) v1(73.66,30.48) v1(73.66,25.4) v1(73.66,20.32) v1(73.66,15.24) v1(73.66,5.08) v1(73.75,6.48) v1(73.89,76.89) v1(74.27,73.36) v1(74.24,71.88) v1(74.24,70.13) v1(74.52,80.95) v1(74.73,77.7) v1(74.75,62.86) v1(74.8,67.64) v1(74.8,6.5) v1(75.21,78.61) v1(75.34,74.75) v1(75.44,96.72) v1(75.41,81.53) v1(75.59,85.24) v1(75.77,6.5) v1(76,79.4) v1(76.07,72.87) v1(76.1,71.6) v1(76.1,70.08) v1(76.2,93.98) v1(76.2,88.9) v1(76.25,75.72) v1(76.28,62.89) v1(76.28,48.08) v1(76.25,43.18) v1(76.2,27.94) v1(76.2,22.86) v1(76.2,17.78) v1(76.2,7.62) v1(76.35,82.17) v1(76.38,53.37) v1(76.4,38.05) v1(76.68,80.42) v1(76.68,58.45) v1(76.68,31.98) v1(76.71,0.51) v1(77.06,73.89) v1(77.37,76.66) v1(77.37,70.13) v1(77.42,62.89) v1(77.8,82.14) v1(77.98,74.8) v1(78.03,6.5) v1(78.13,80.42) v1(78.16,35.51) v1(78.54,62.86) v1(78.61,76.66) v1(78.64,70.13) v1(78.74,91.44) v1(78.79,86.79) v1(78.74,40.64) v1(78.74,30.48) v1(78.74,25.4) v1(78.74,20.32) v1(78.74,15.24) v1(79.02,6.48) v1(79.25,96.72) v1(79.22,10.79) v1(79.3,82.17) v1(79.38,80.39) v1(79.38,68.15) v1(79.3,64.82) v1(79.78,74.78) v1(79.76,70.1) v1(79.73,62.89) v1(79.98,76.66) v1(79.98,6.48) v1(80.26,34.14) v1(80.52,0.51) v1(80.67,82.19) v1(80.67,80.39) v1(80.67,66.47) v1(80.72,67.97) v1(80.72,65.05) v1(80.82,73.76) v1(80.95,77.62) v1(80.9,70.1) v1(80.95,62.89) v1(81.28,93.98) v1(81.28,88.9) v1(81.28,53.34) v1(81.28,48.26) v1(81.28,43.18) v1(81.28,27.94) v1(81.28,22.86) v1(81.28,17.78) v1(81.28,7.62) v1(81.28,2.54) v1(81.76,58.45) v1(81.99,65.02) v1(82.04,77.9) v1(82.14,70.08) v1(82.12,67.94) v1(82.17,62.89) v1(82.37,85.42) v1(82.3,73.33) v1(82.52,66.45) v1(83.06,96.72) v1(83.36,70.1) v1(83.36,68.12) v1(83.39,64.87) v1(83.36,62.89) v1(83.52,78.03) v1(83.72,73.28) v1(83.82,91.44) v1(83.82,30.48) v1(83.82,25.4) v1(83.82,20.32) v1(83.82,15.24) v1(83.95,10.82) v1(84.07,86.79) v1(84.35,70.41) v1(84.3,39.85) v1(84.33,0.51) v1(84.46,65.3) v1(84.76,62.56) v1(84.76,32.16) v1(84.86,77.19) v1(84.96,74.14) v1(85.7,70.43) v1(85.93,62.56) v1(86.06,34.14) v1(86.11,77.17) v1(86.28,74.17) v1(86.36,93.98) v1(86.36,88.9) v1(86.36,58.42) v1(86.36,53.34) v1(86.36,48.26) v1(86.36,43.18) v1(86.36,27.94) v1(86.36,22.86) v1(86.36,17.78) v1(86.36,2.54) v1(86.46,75.64) v1(86.51,81.71) v1(86.87,96.72) v1(87.38,77.14) v1(87.38,7.62) v1(88.04,39.52) v1(88.14,0.51) v1(88.57,77.11) v1(88.67,86.72) v1(88.85,74.4) v1(88.87,62.56) v1(88.9,91.44) v1(88.9,30.48) v1(88.9,25.4) v1(88.9,20.32) v1(88.9,15.24) v1(88.93,10.82) v1(88.9,5.08) v1(89.74,70.43) v1(89.94,34.06) v1(90.02,62.53) v1(90.25,53.49) v1(90.4,74.37) v1(90.68,96.72) v1(90.88,65.33) v1(90.96,67.61) v1(91.36,70.41) v1(91.34,62.51) v1(91.44,93.98) v1(91.44,88.9) v1(91.44,58.42) v1(91.44,48.26) v1(91.44,43.18) v1(91.44,27.94) v1(91.44,22.86) v1(91.44,17.78) v1(91.44,7.62) v1(91.44,2.54) v1(91.54,10.19) v1(91.95,0.51) v1(92.14,67.59) v1(92.2,65.18) v1(92.41,83.67) v1(92.53,40.31) v1(92.66,62.66) v1(92.86,70.28) v1(92.86,66.42) v1(93.19,53.49) v1(93.51,67.56) v1(93.52,65.18) v1(93.62,74.45) v1(93.73,34.11) v1(93.98,91.44) v1(93.98,86.36) v1(93.98,30.48) v1(93.98,25.4) v1(93.98,10.16) v1(93.98,5.08) v1(94.16,62.56) v1(94.49,96.72) v1(94.51,70.43) v1(94.65,76.58) v1(94.65,75.67) v1(94.79,40.39) v1(94.84,65.33) v1(94.92,67.59) v1(94.92,20.22) v1(95.11,76.12) v1(95.25,51.38) v1(95.4,56.21) v1(95.56,76.58) v1(95.56,75.67) v1(95.61,62.53) v1(95.76,0.51) v1(96.39,70.43) v1(96.52,93.98) v1(96.52,88.9) v1(96.52,83.82) v1(96.55,77.75) v1(96.52,58.42) v1(96.52,35.56) v1(96.52,7.62) v1(96.52,2.54) v1(96.67,74.57) v1(97.25,62.53) v1(97.79,38.73) v1(97.79,27.84) v1(97.89,70.41) v1(97.82,23.01) v1(97.92,63.93) v1(98.04,54.58) v1(98.12,79.1) v1(98.3,96.72) v1(98.55,11.56) v1(98.55,8.13) v1(98.55,4.32) v1(98.55,0.51) v1(98.81,50.83) v1(99.06,91.44) v1(99.06,86.36) v1(99.06,15.24) v1(99.19,70.41) v1(99.39,83.52) v1(99.44,62.53) v1(100.08,30.78) v1(100.08,26.11) v1(100.23,76.78) v1(100.36,79.45) v1(100.41,74.37) v1(100.71,70.43) v1(101.09,62.53) v1(101.52,76.05) v1(101.6,93.98) v1(101.6,88.9) v1(101.6,83.82) v1(101.6,78.99) v1(101.63,77.24) v1(101.68,74.32) v1(101.6,58.42) v1(101.6,17.78) v1(102.11,96.72) v1(102.26,23.9) v1(102.31,70.26) v1(102.36,65.2) v1(102.39,62.69) v1(102.31,29.21) v1(102.44,33.88) v1(102.67,67.79) v1(102.64,66.62) v1(102.74,78.99) v1(102.77,76.02) v1(102.82,77.27) v1(103,13.21) v1(103.43,65.66) v1(103.56,53.31) v1(103.68,76.66) v1(104.14,91.44) v1(104.14,86.36) v1(104.14,81.28) v1(104.14,38.1) v1(104.14,20.32) v1(104.14,15.24) v1(104.47,67.74) v1(104.52,65.2) v1(104.62,78.46) v1(104.78,70.84) v1(104.83,74.24) v1(105.08,77.57) v1(105.03,75.62) v1(105.38,62.86) v1(105.51,71.58) v1(105.74,74.9) v1(105.74,73.89) v1(105.87,66.5) v1(105.97,77.29) v1(106.07,68.15) v1(106.07,64.8) v1(106.2,96.72) v1(106.45,69.88) v1(106.58,63.07) v1(106.68,93.98) v1(106.68,88.9) v1(106.68,83.82) v1(106.68,58.42) v1(106.68,50.8) v1(106.68,33.02) v1(106.68,27.94) v1(106.68,22.86) v1(106.68,17.78) v1(106.76,76.48) v1(106.81,13.21) v1(107.57,75.44) v1(107.57,73.89) v1(107.59,72.8) v1(107.57,71.45) v1(107.54,68.15) v1(107.54,64.77) v1(107.67,63.07) v1(107.7,69.85) v1(108.59,44.45) v1(108.76,63.07) v1(108.84,70.56) v1(108.86,68.15) v1(108.99,64.8) v1(108.99,48.44) v1(109.22,91.44) v1(109.22,86.36) v1(109.22,81.28) v1(109.22,53.34) v1(109.22,30.48) v1(109.22,25.4) v1(109.22,20.32) v1(109.22,15.24) v1(109.47,96.72) v1(109.75,68.99) v1(109.75,62.1) v1(109.83,71.58) v1(110.11,64.14) v1(110.62,13.21) v1(110.72,72.47) v1(110.77,61.04) v1(110.85,70.08) v1(111.15,63.14) v1(111.63,60.15) v1(111.76,93.98) v1(111.76,83.82) v1(111.76,78.74) v1(111.79,73.48) v1(111.76,50.8) v1(111.76,33.02) v1(111.76,27.94) v1(111.76,22.86) v1(111.76,17.78) v1(111.81,88.98) v1(112.01,71.3) v1(112.29,96.75) v1(112.27,62.05) v1(112.6,59.21) v1(112.78,74.47) v1(112.95,72.19) v1(113.18,61.11) v1(113.69,75.34) v1(113.69,72.95) v1(113.74,58.09) v1(114,60.3) v1(114.3,53.34) v1(114.3,48.26) v1(114.3,30.48) v1(114.3,25.4) v1(114.3,13.21) v1(114.5,73.74) v1(114.76,81.23) v1(114.94,96.7) v1(115.01,59.39) v1(115.14,57.66) v1(115.32,75.46) v1(115.72,73.74) v1(116.56,93.98) v1(116.51,57.66) v1(116.69,75.44) v1(116.64,73.74) v1(116.64,59.41) v1(116.84,83.82) v1(116.84,50.8) v1(116.84,33.02) v1(116.84,27.94) v1(116.84,22.86) v1(117.14,78.89) v1(117.17,66.07) v1(117.55,75.82) v1(117.6,73.3) v1(117.73,57.43) v1(117.86,96.7) v1(118.57,59.92) v1(118.72,57.43) v1(118.8,75.82) v1(118.82,73.3) v1(119.38,81.28) v1(119.38,48.26) v1(119.38,30.48) v1(119.38,25.4) v1(119.41,69.77) v1(119.48,66.27) v1(119.94,57.45) v1(120.04,73.3) v1(120.04,59.94) v1(120.14,75.82) v1(121.39,75.82) v1(121.39,73.3) v1(121.41,96.7) v1(121.41,93.65) v1(121.41,90.8) v1(121.41,88.29) v1(121.41,86.44) v1(121.41,84.4) v1(121.41,82.55) v1(121.44,81.18) v1(121.41,79.76) v1(121.41,69.98) v1(121.41,67.94) v1(121.41,65.53) v1(121.41,63.25) v1(121.41,59.94) v1(121.44,57.43) v1(121.41,55.63) v1(121.41,50.29) v1(121.41,46.48) v1(121.41,42.67) v1(121.41,38.86) v1(121.41,35.05) v1(121.41,31.24) v1(121.41,27.43) v1(121.41,23.62) v1(121.41,19.81) v2(0.56,78.26) v2(0.56,77.37) v2(0.56,76.48) v2(0.56,72.69) v2(0.56,71.81) v2(0.56,70.92) v2(0.56,62.38) v2(0.56,61.49) v2(0.56,60.6) v2(0.56,56.82) v2(0.56,55.93) v2(0.56,55.04) v2(1.32,78.26) v2(1.32,77.37) v2(1.32,76.48) v2(1.32,72.69) v2(1.32,71.81) v2(1.32,70.92) v2(1.32,62.38) v2(1.32,61.49) v2(1.32,60.6) v2(1.32,56.82) v2(1.32,55.93) v2(1.32,55.04) v2(2.21,78.28) v2(2.21,77.37) v2(2.21,76.5) v2(2.21,72.72) v2(2.21,71.81) v2(2.21,70.94) v2(2.21,62.41) v2(2.21,61.49) v2(2.21,60.63) v2(2.21,56.85) v2(2.21,55.93) v2(2.21,55.07) v2(3.1,78.28) v2(3.1,77.39) v2(3.1,76.5) v2(3.1,72.72) v2(3.1,71.83) v2(3.1,70.94) v2(3.1,62.41) v2(3.1,61.52) v2(3.1,60.63) v2(3.1,56.85) v2(3.1,55.96) v2(3.1,55.07) v2(3.86,78.28) v2(3.86,77.39) v2(3.86,76.5) v2(3.86,72.72) v2(3.86,71.83) v2(3.86,70.94) v2(3.86,62.41) v2(3.86,61.52) v2(3.86,60.63) v2(3.86,56.85) v2(3.86,55.96) v2(3.86,55.07) v2(15.85,55.04) v2(15.85,54.34) v2(16.55,56.44) v2(16.55,55.74) v2(16.55,55.04) v2(16.55,54.34) v2(16.55,53.64) v2(17.25,56.44) v2(17.25,55.74) v2(17.25,55.04) v2(17.25,54.34) v2(17.25,53.64) v2(17.95,56.44) v2(17.95,55.74) v2(17.95,55.04) v2(17.95,54.34) v2(17.95,53.64) v2(18.65,56.44) v2(18.65,55.74) v2(18.65,55.04) v2(18.65,54.34) v2(22.98,45.59) v2(22.98,44.19) v2(23.68,46.99) v2(23.68,46.29) v2(23.68,45.59) v2(23.68,44.89) v2(23.68,44.19) v2(24.38,46.99) v2(24.38,46.29) v2(24.38,45.59) v2(24.38,44.89) v2(24.38,44.19) v2(25.08,46.29) v2(25.08,45.59) v2(25.08,44.89) v2(25.08,44.19) v2(25.78,46.29) v2(25.78,45.59) v2(25.78,44.89) v2(25.78,44.19) v2(117.92,78.21) v2(117.92,77.32) v2(117.92,76.43) v2(117.92,72.64) v2(117.92,71.75) v2(117.92,70.87) v2(117.92,62.33) v2(117.92,61.44) v2(117.92,60.55) v2(117.92,56.77) v2(117.92,55.88) v2(117.92,54.99) v2(118.68,78.21) v2(118.68,77.32) v2(118.68,76.43) v2(118.68,72.64) v2(118.68,71.75) v2(118.68,70.87) v2(118.68,62.33) v2(118.68,61.44) v2(118.68,60.55) v2(118.68,56.77) v2(118.68,55.88) v2(118.68,54.99) v2(119.57,78.21) v2(119.57,77.34) v2(119.57,76.43) v2(119.57,72.64) v2(119.57,71.78) v2(119.57,70.87) v2(119.57,62.33) v2(119.57,61.47) v2(119.57,60.55) v2(119.57,56.77) v2(119.57,55.91) v2(119.57,54.99) v2(120.46,78.23) v2(120.46,77.34) v2(120.46,76.45) v2(120.46,72.67) v2(120.46,71.78) v2(120.46,70.89) v2(120.46,62.36) v2(120.46,61.47) v2(120.46,60.58) v2(120.46,56.79) v2(120.46,55.91) v2(120.46,55.02) v2(121.22,78.23) v2(121.22,77.34) v2(121.22,76.45) v2(121.22,72.67) v2(121.22,71.78) v2(121.22,70.89) v2(121.22,62.36) v2(121.22,61.47) v2(121.22,60.58) v2(121.22,56.79) v2(121.22,55.91) v2(121.22,55.02) v3(34.22,27.07) v3(34.21,26.63) v3(34.21,26.2) v3(34.21,25.76) v3(34.62,26.63) v3(34.62,25.76)
